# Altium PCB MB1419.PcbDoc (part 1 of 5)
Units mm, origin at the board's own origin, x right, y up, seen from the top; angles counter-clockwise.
Board outline 31 x 41 mm, 8 copper layers (Top Layer, Signal Layer 1, Signal Layer 2, Signal Layer 3, Signal Layer 4, Signal Layer 5, Signal Layer 6, Bottom Layer), stack 1.536 mm thick; 212 components, 125 nets, 637 pads, 2405 vias.
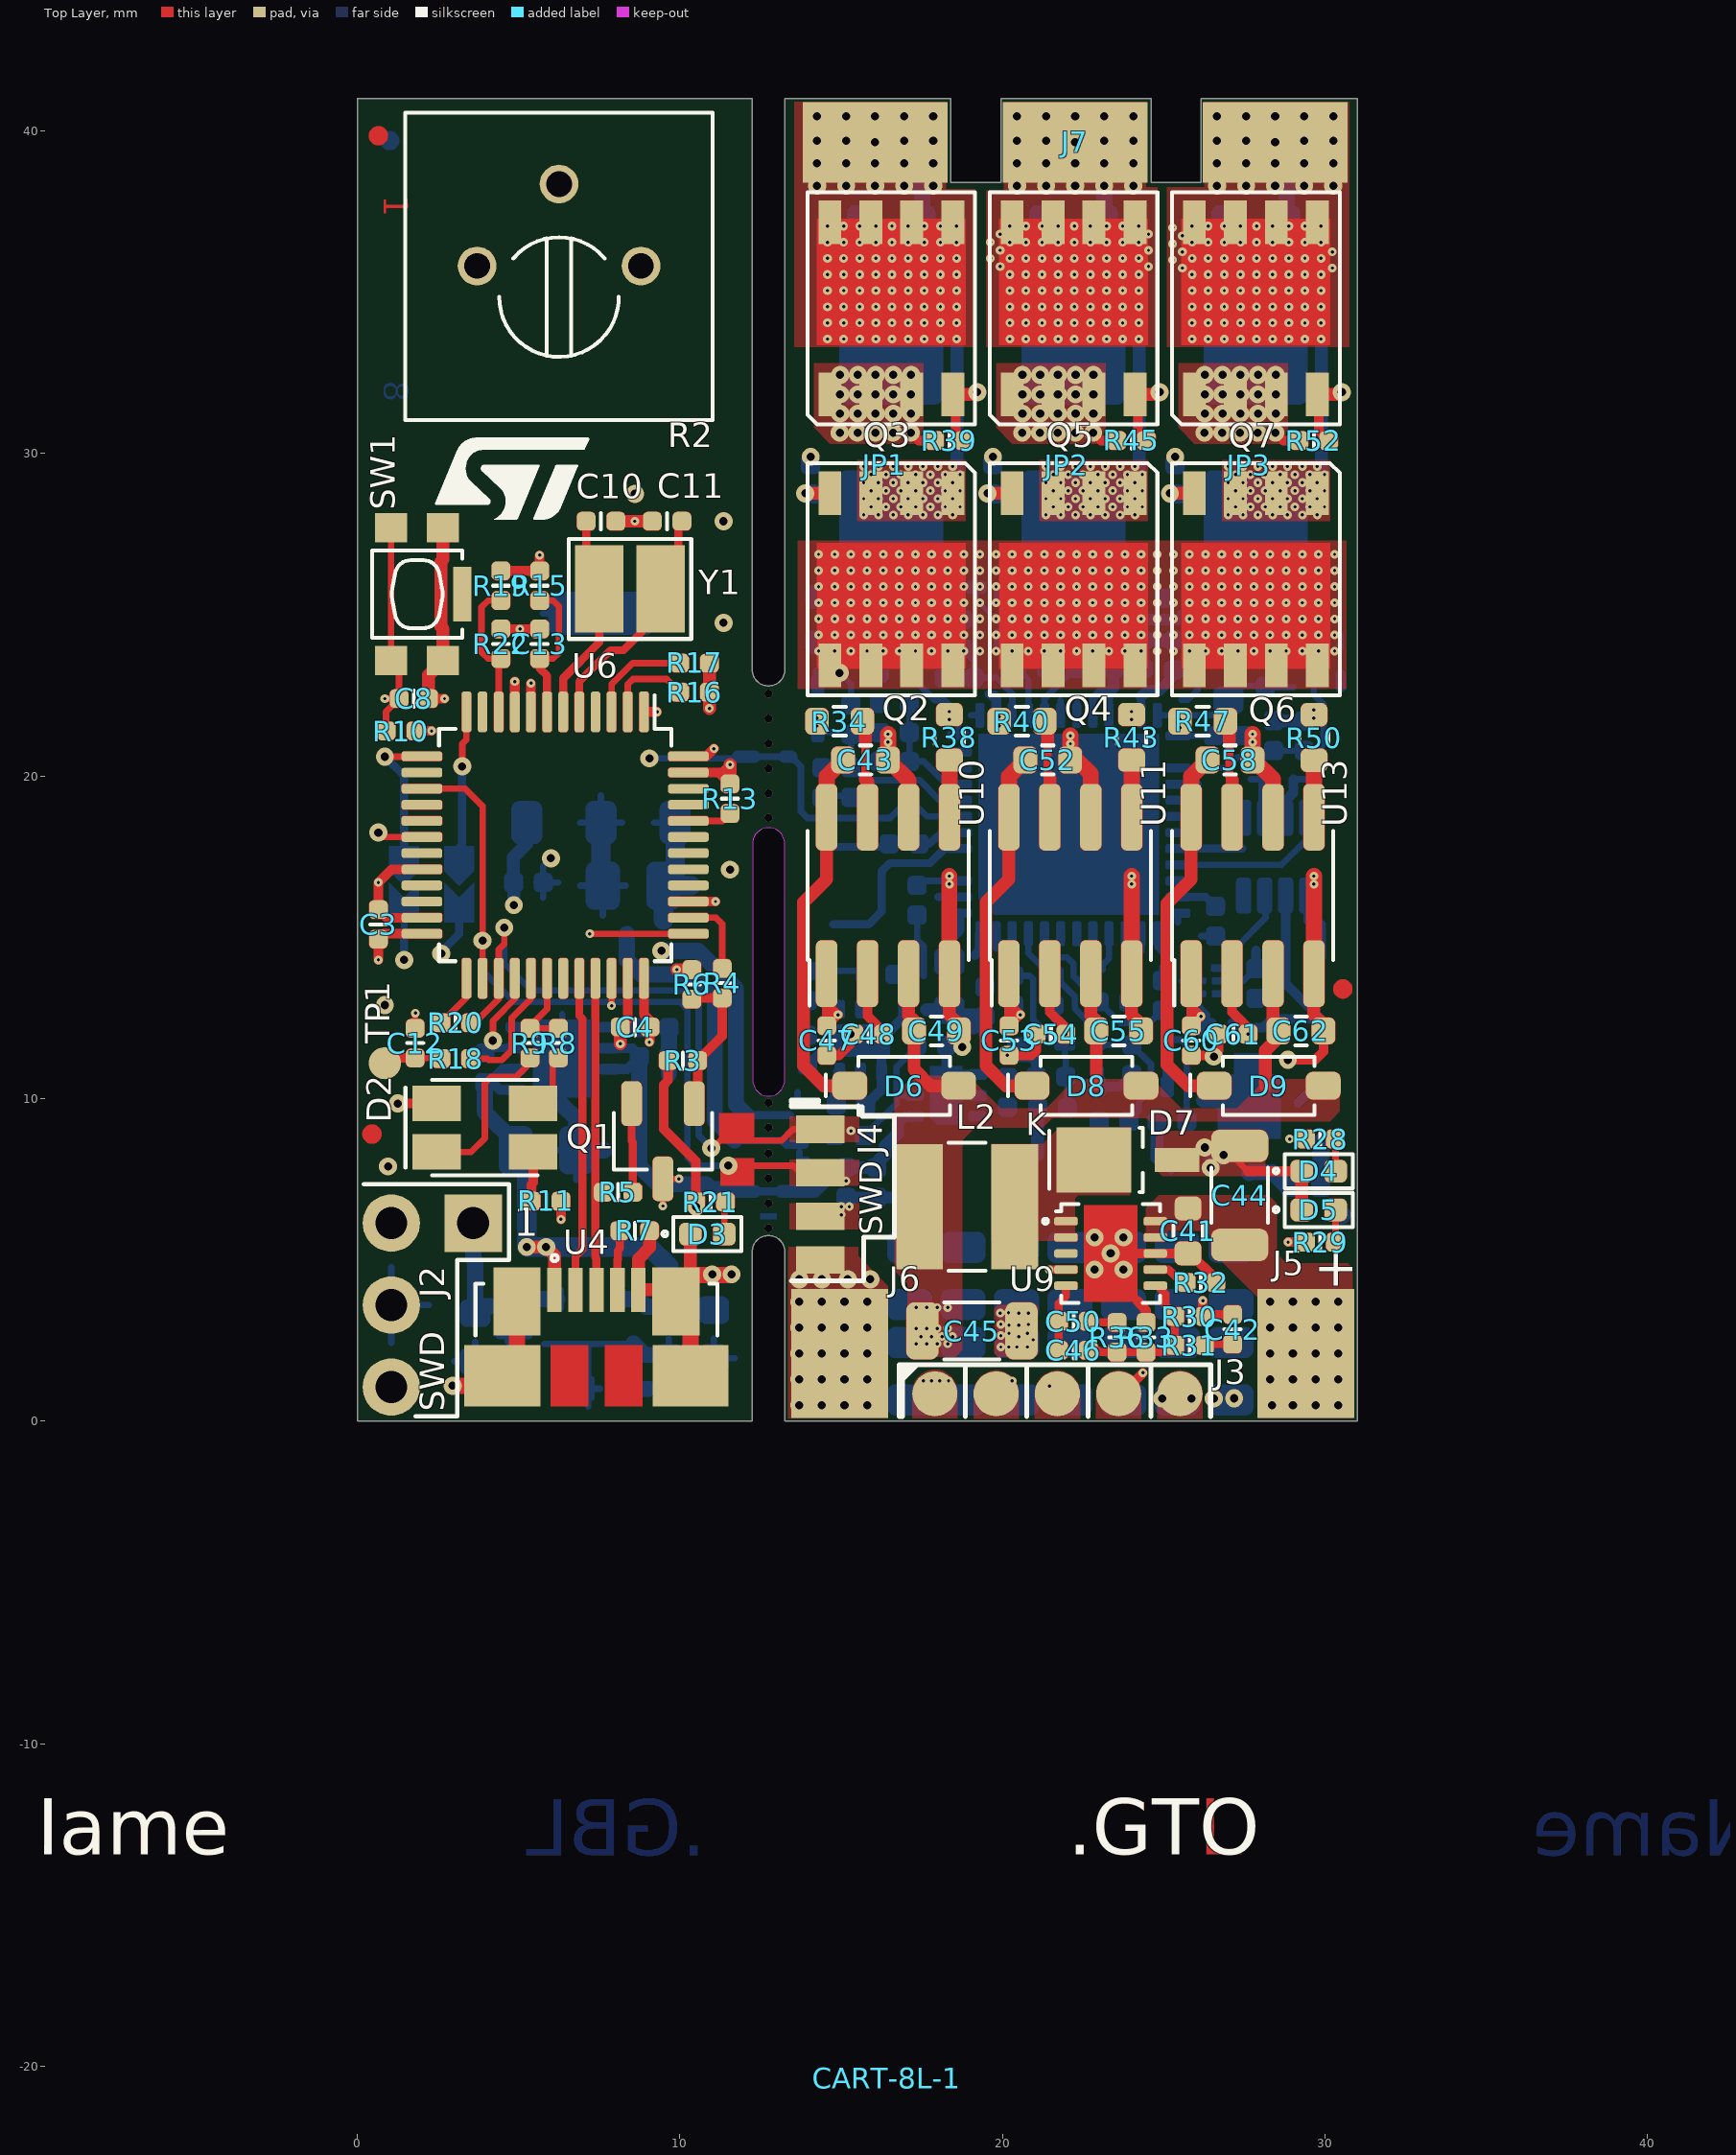
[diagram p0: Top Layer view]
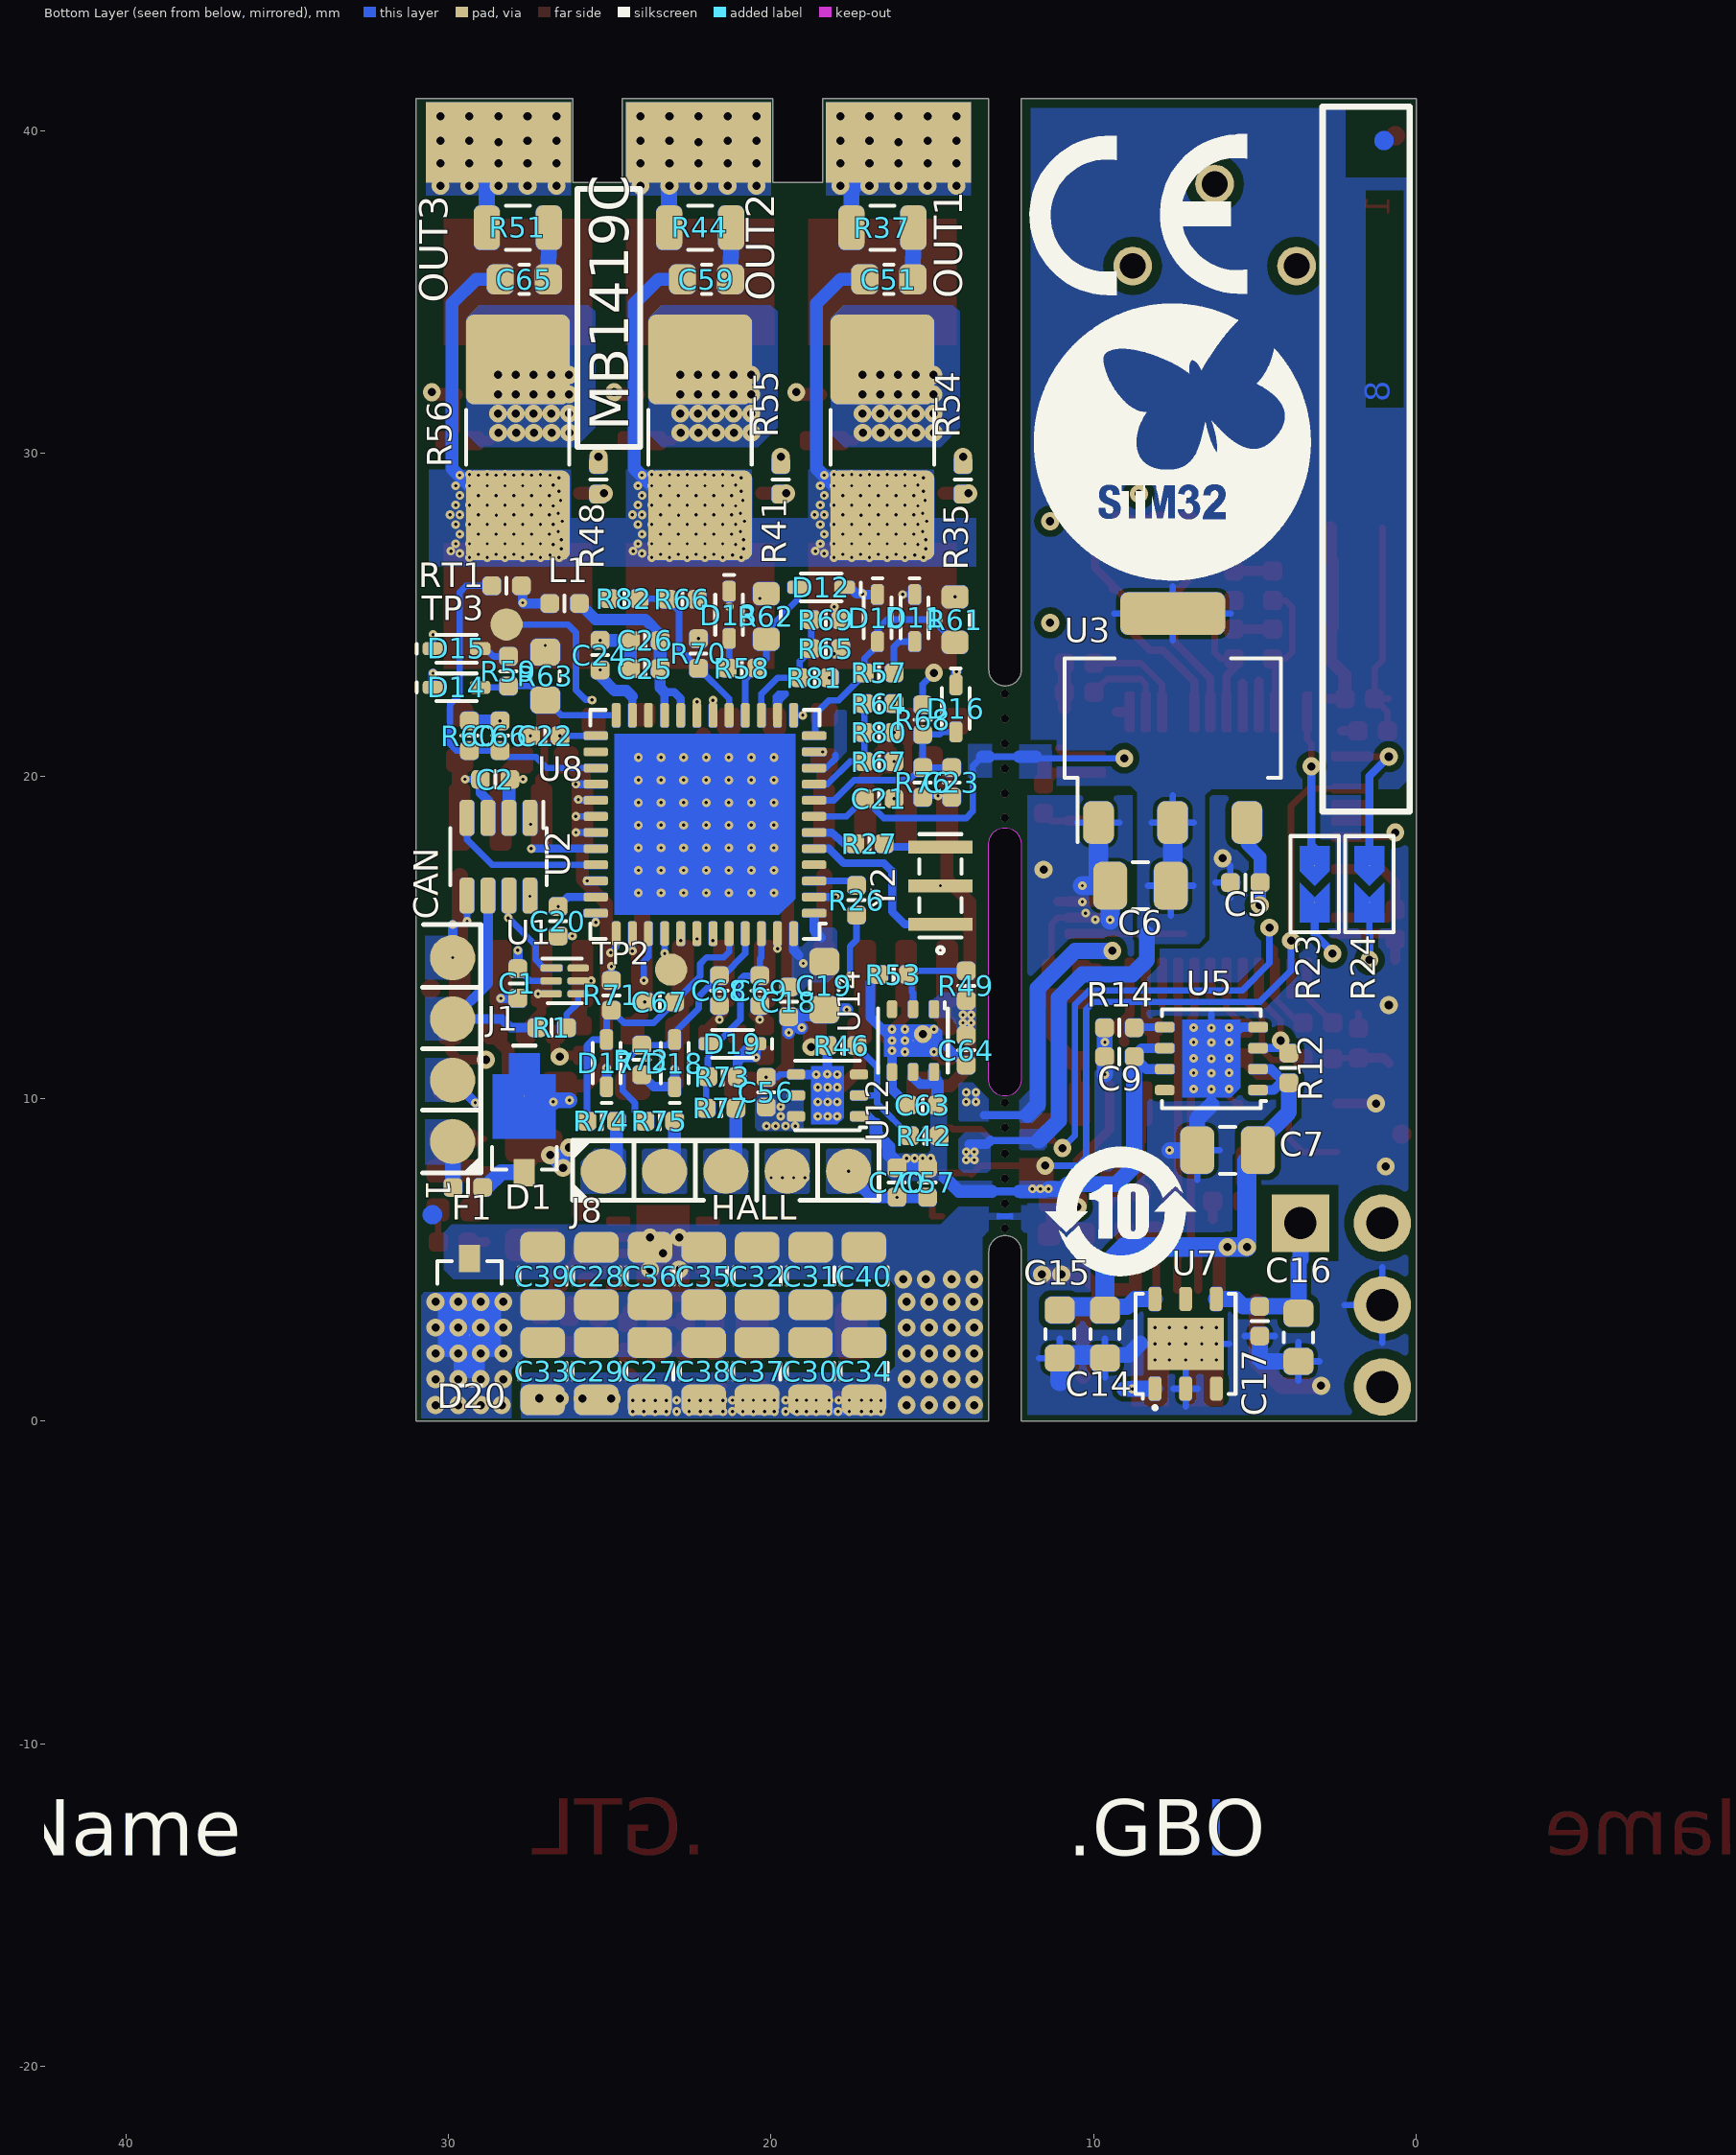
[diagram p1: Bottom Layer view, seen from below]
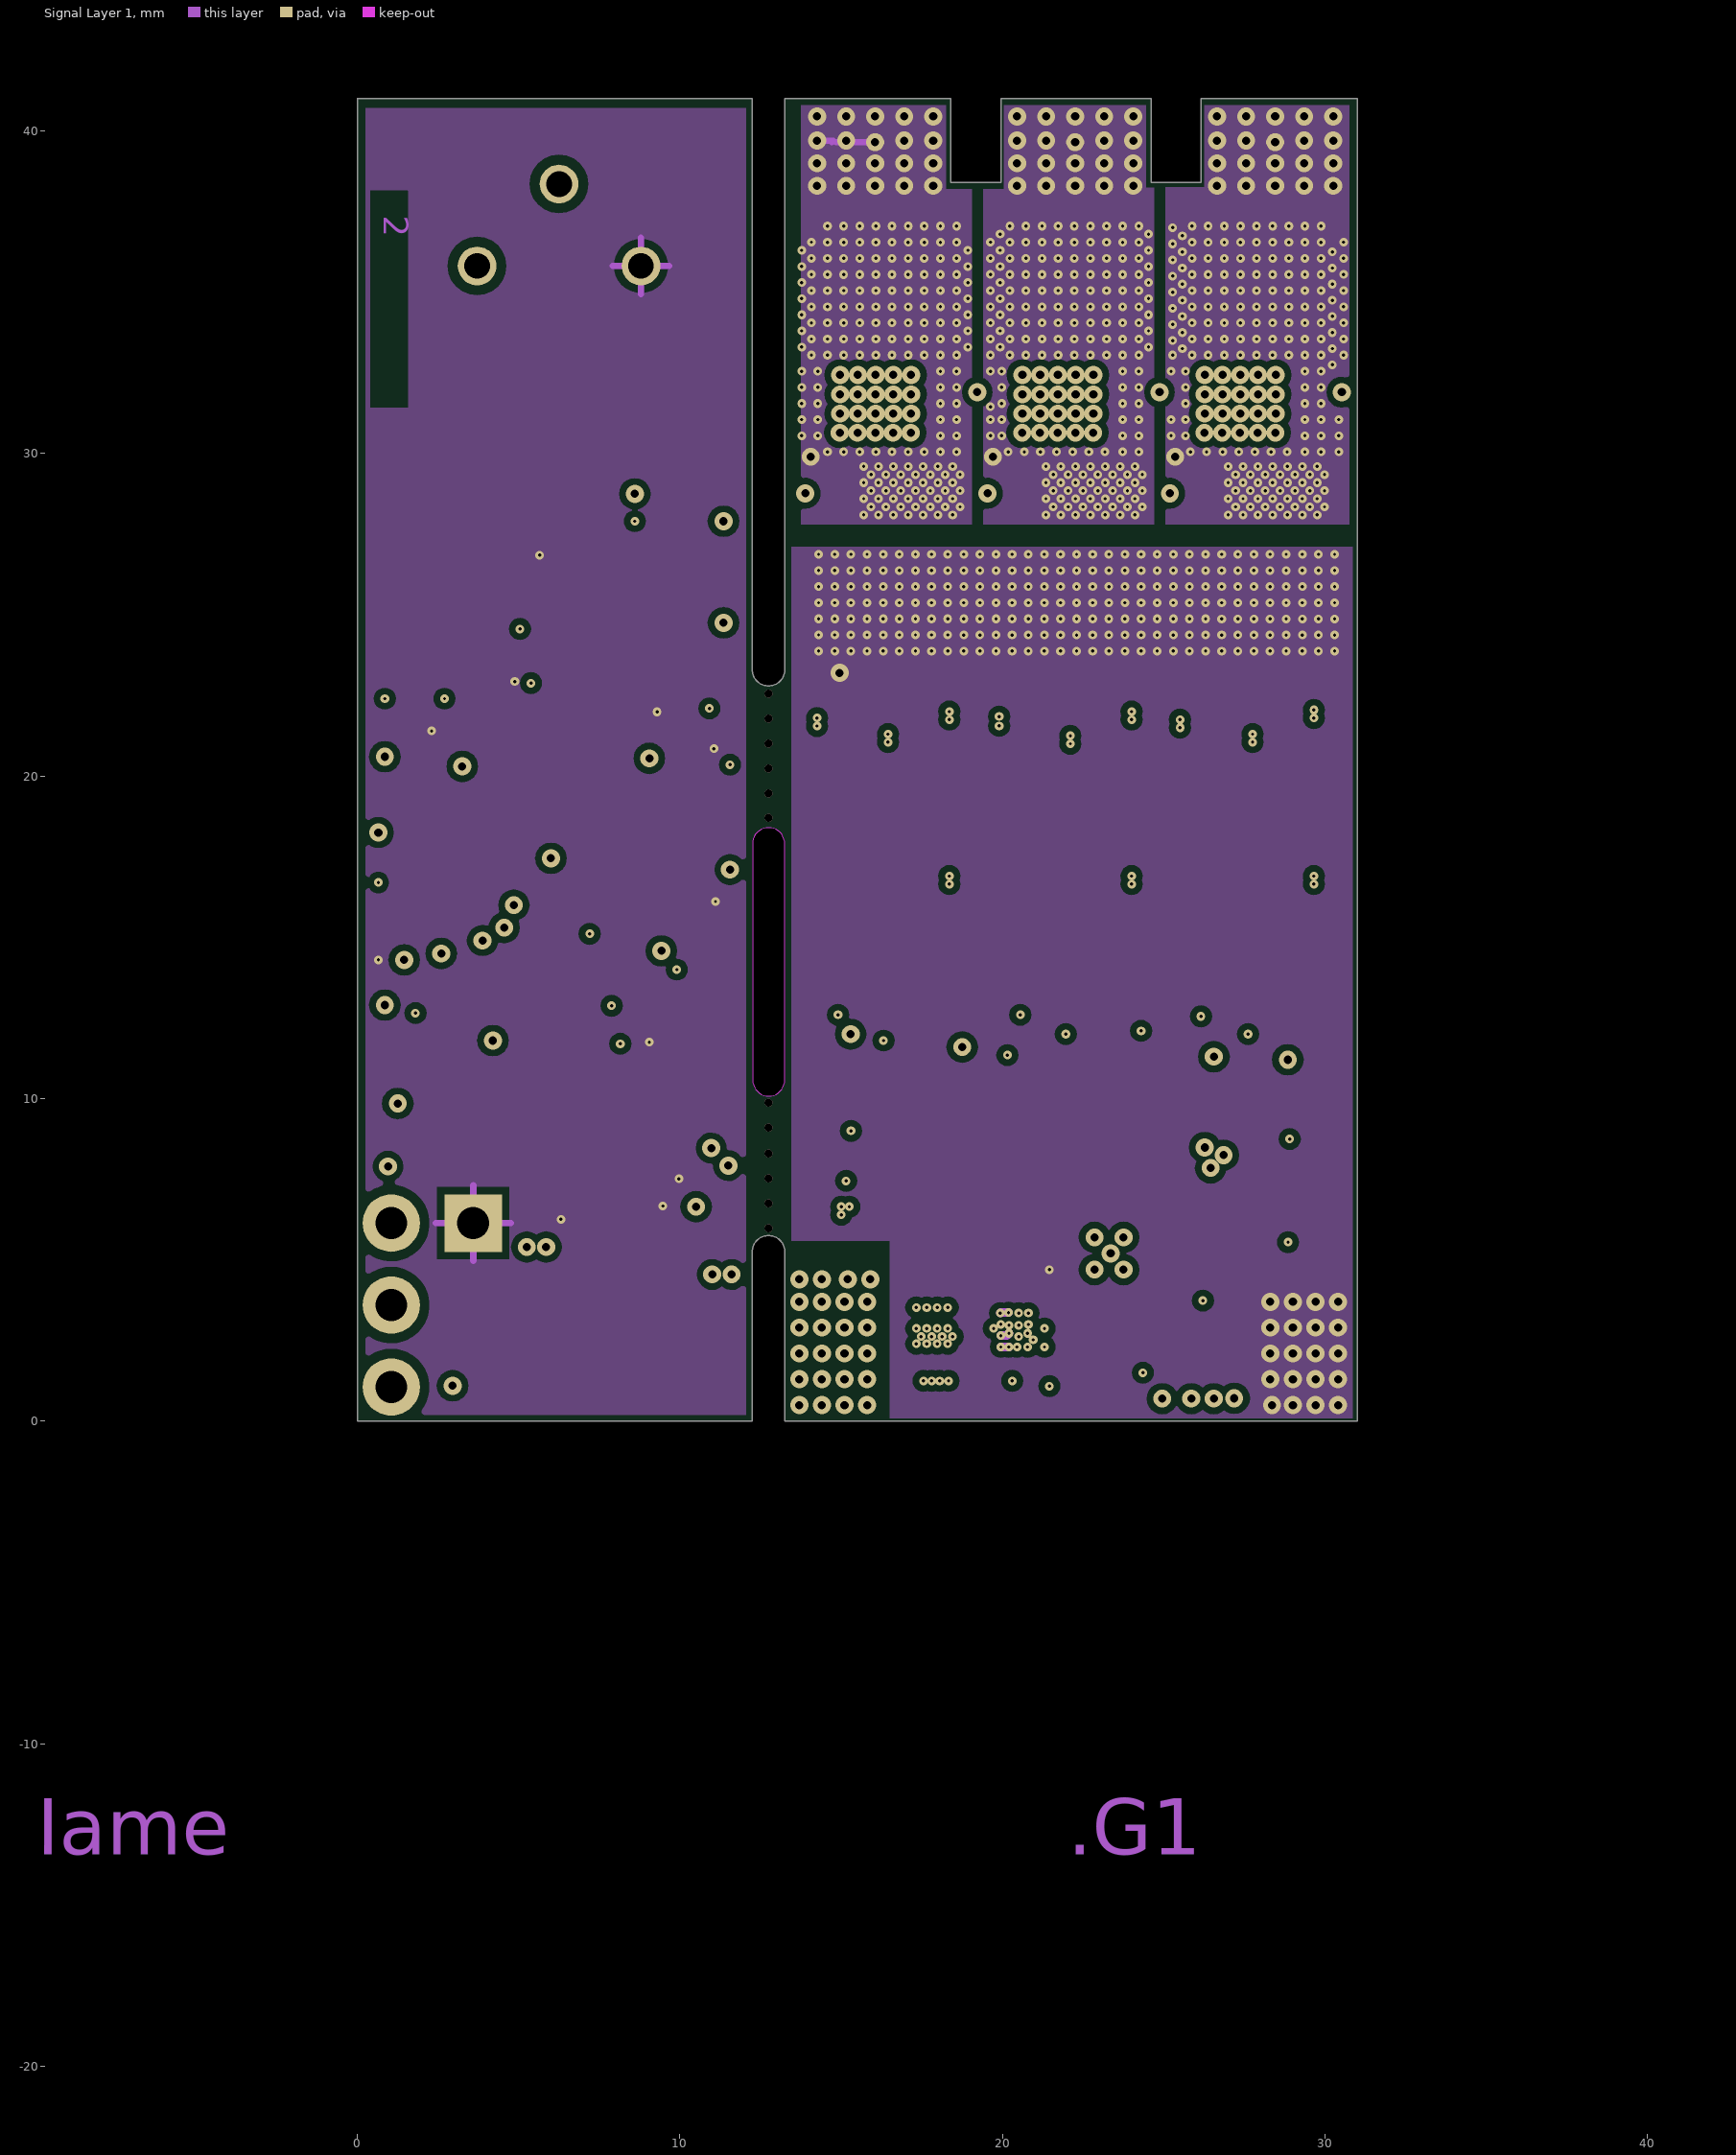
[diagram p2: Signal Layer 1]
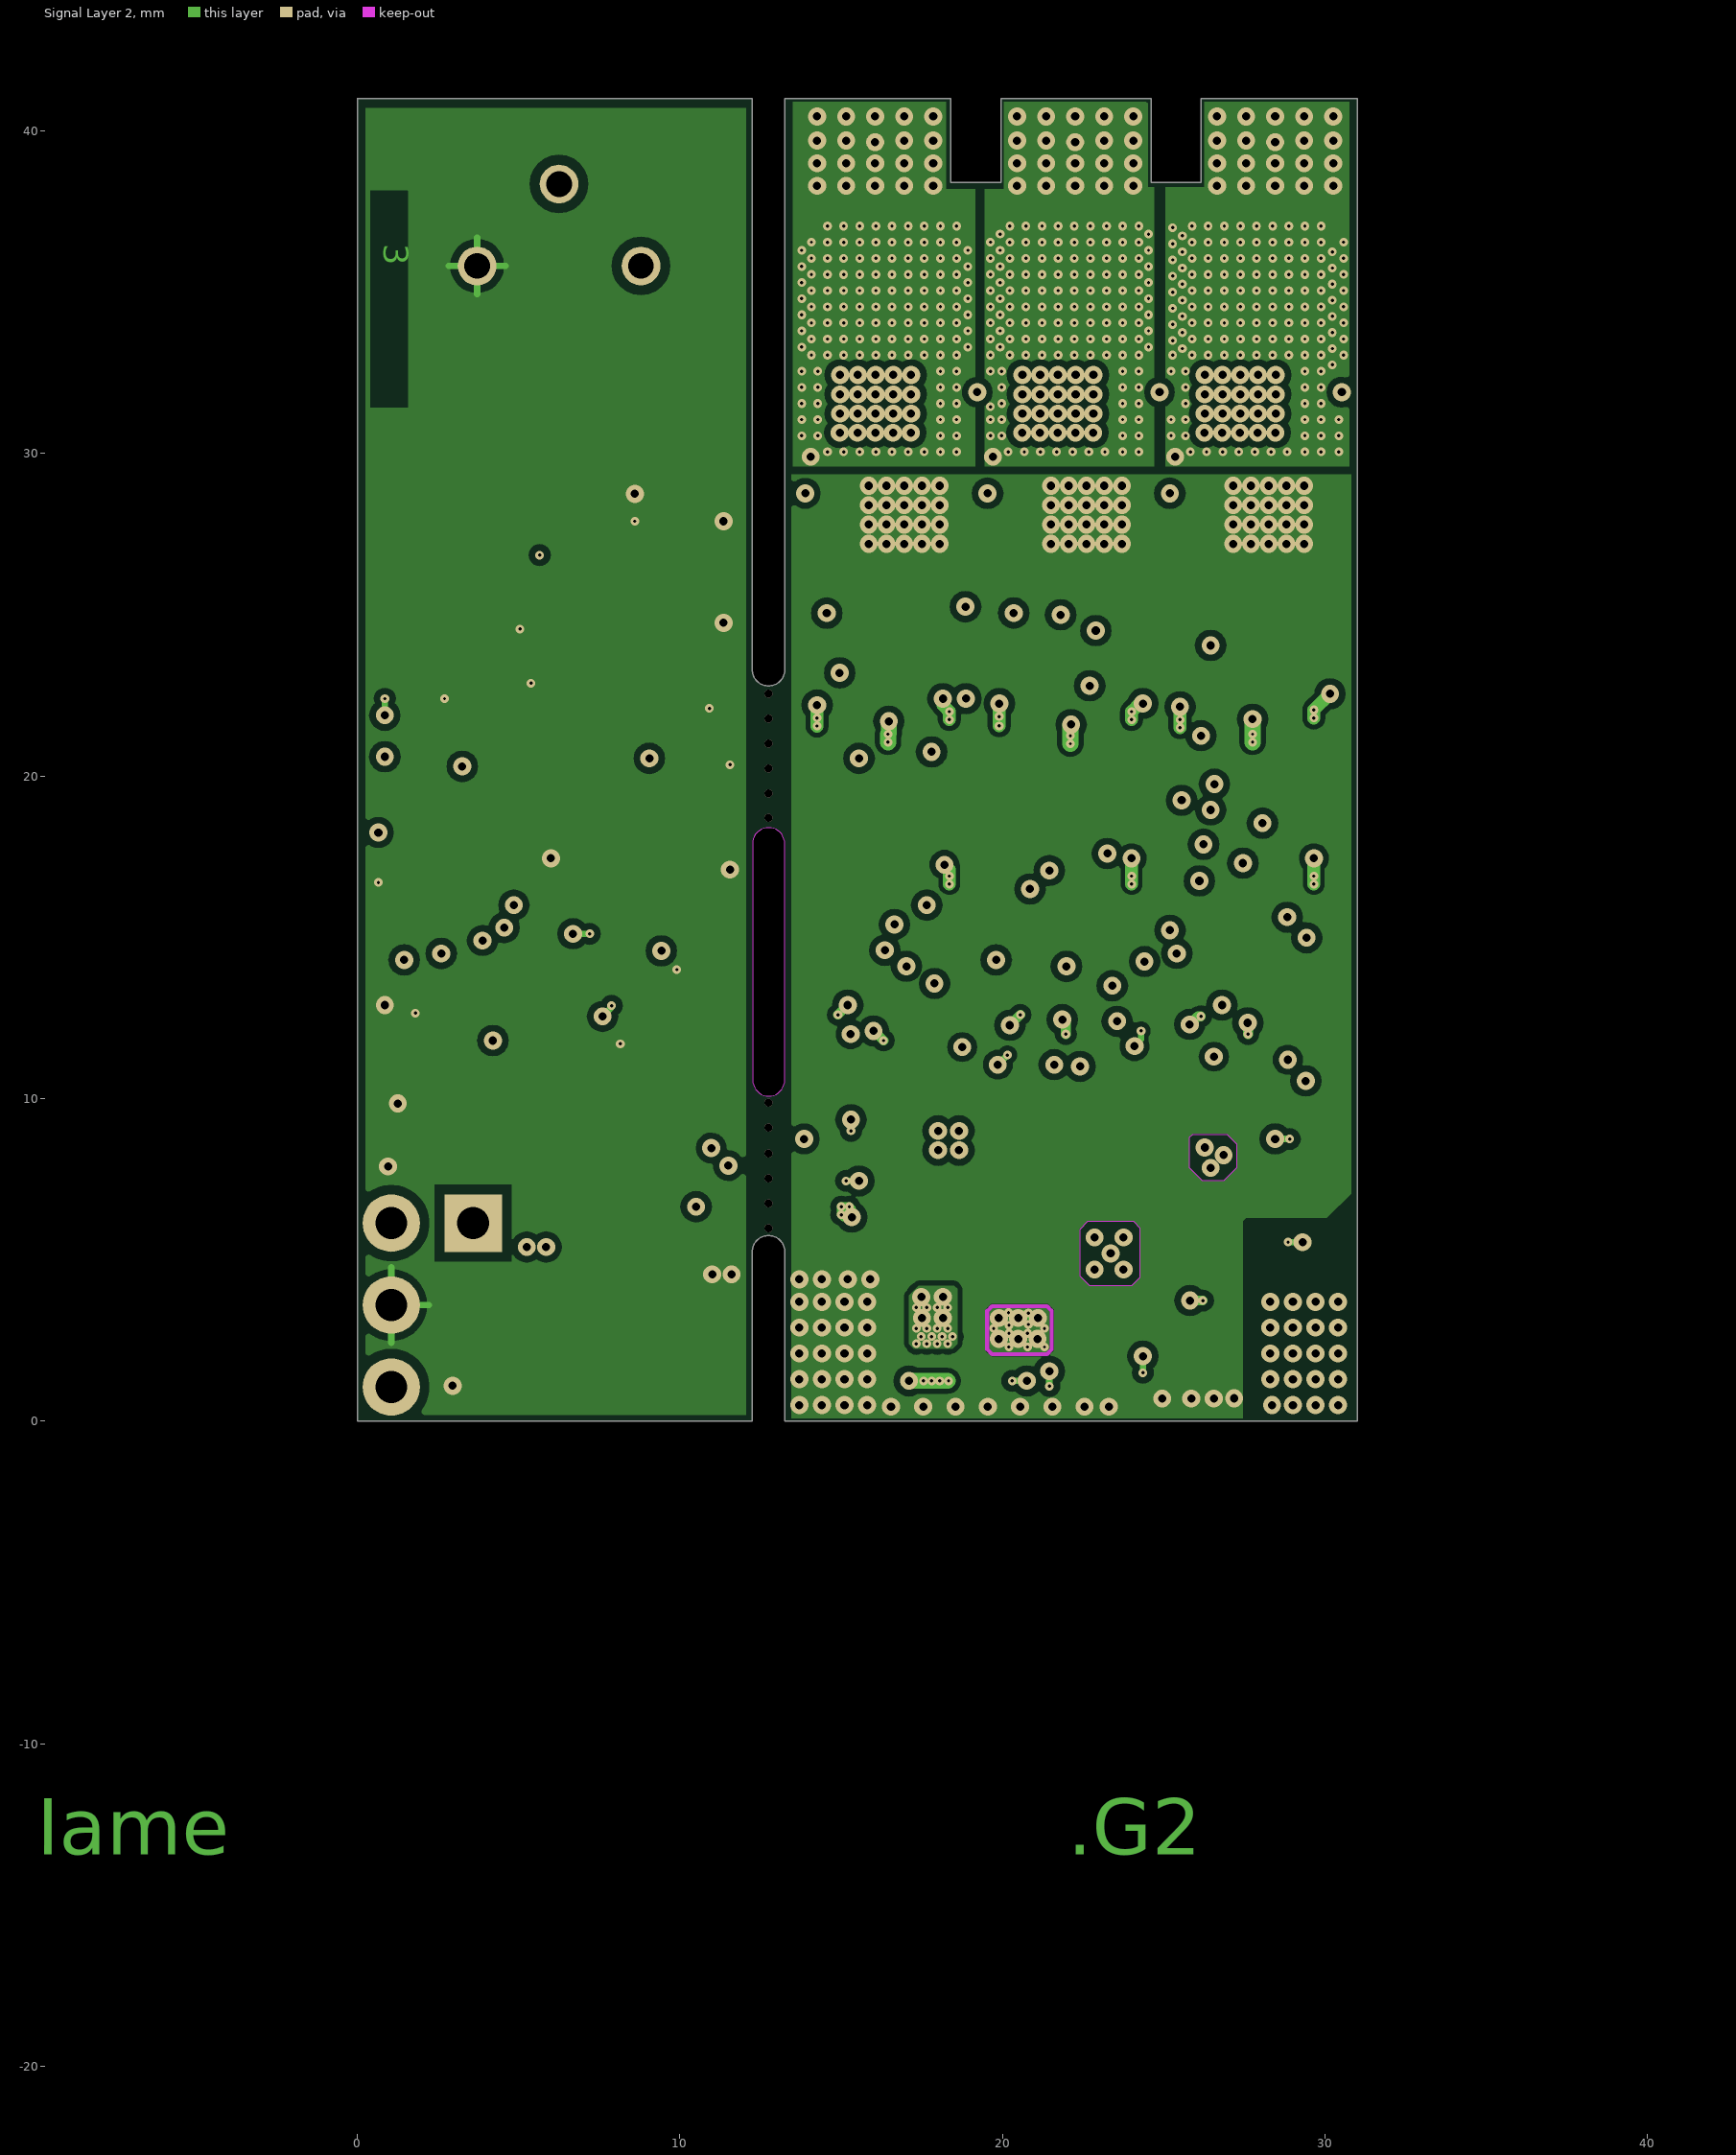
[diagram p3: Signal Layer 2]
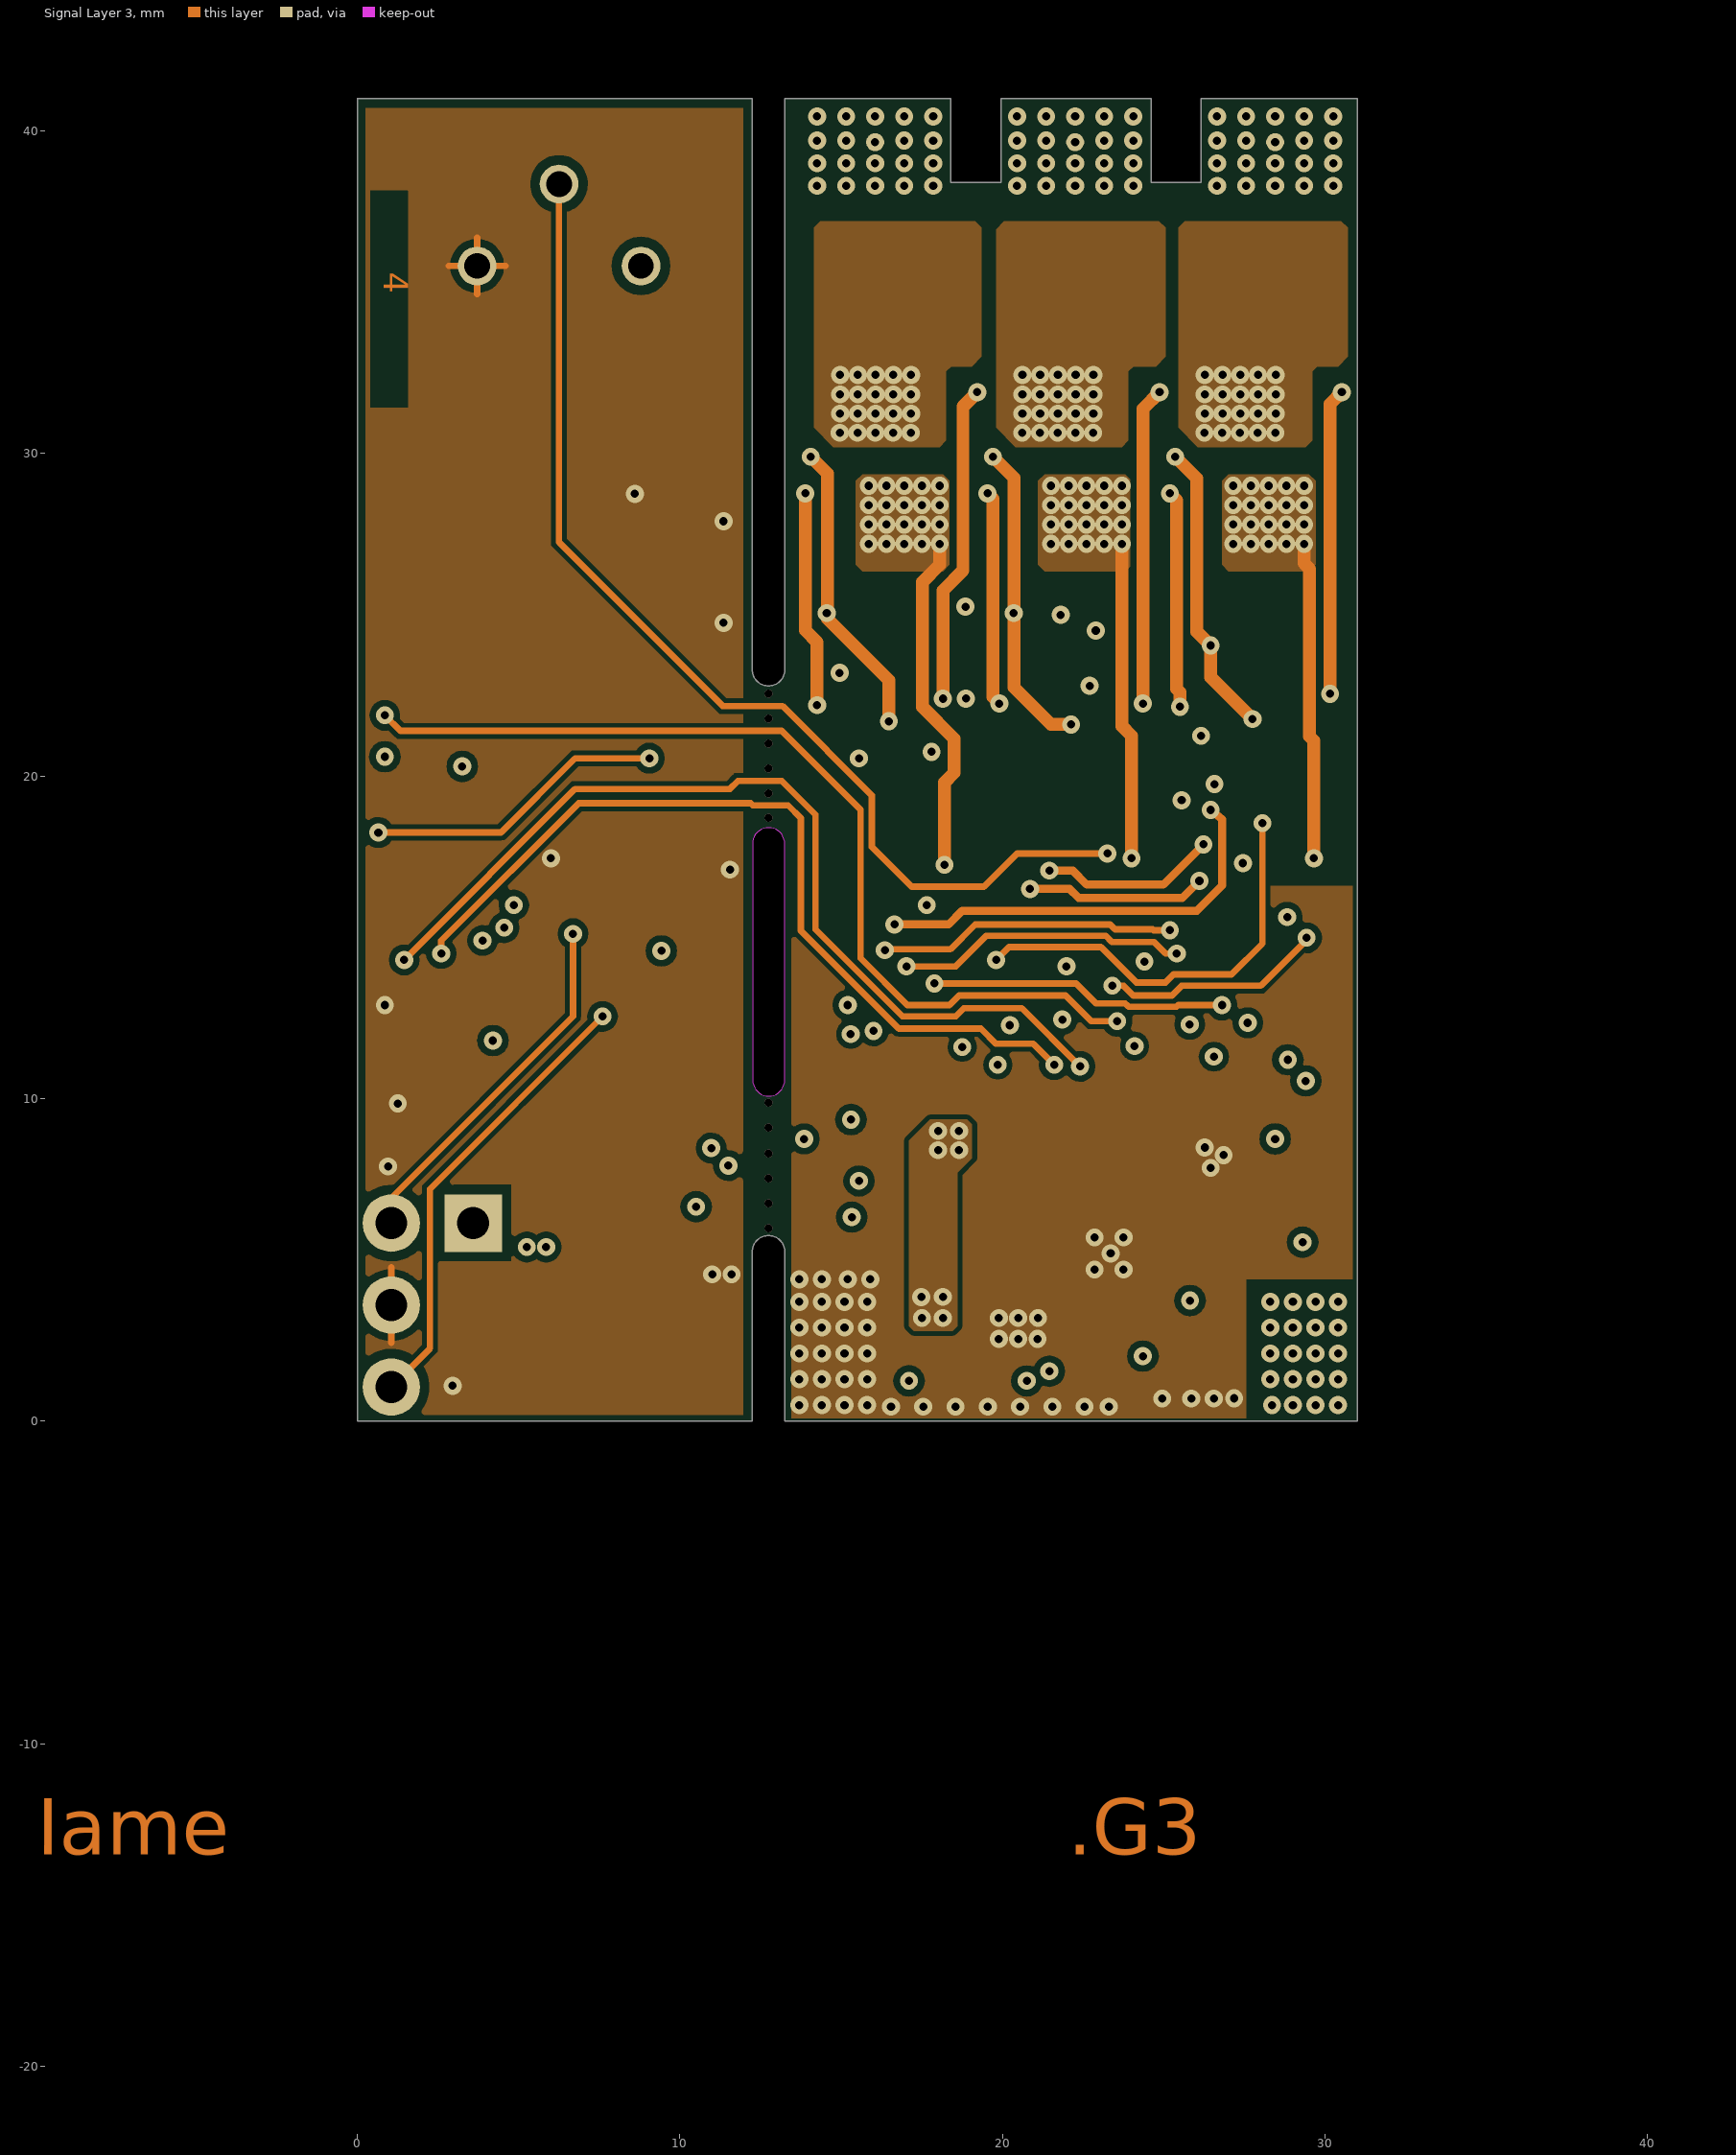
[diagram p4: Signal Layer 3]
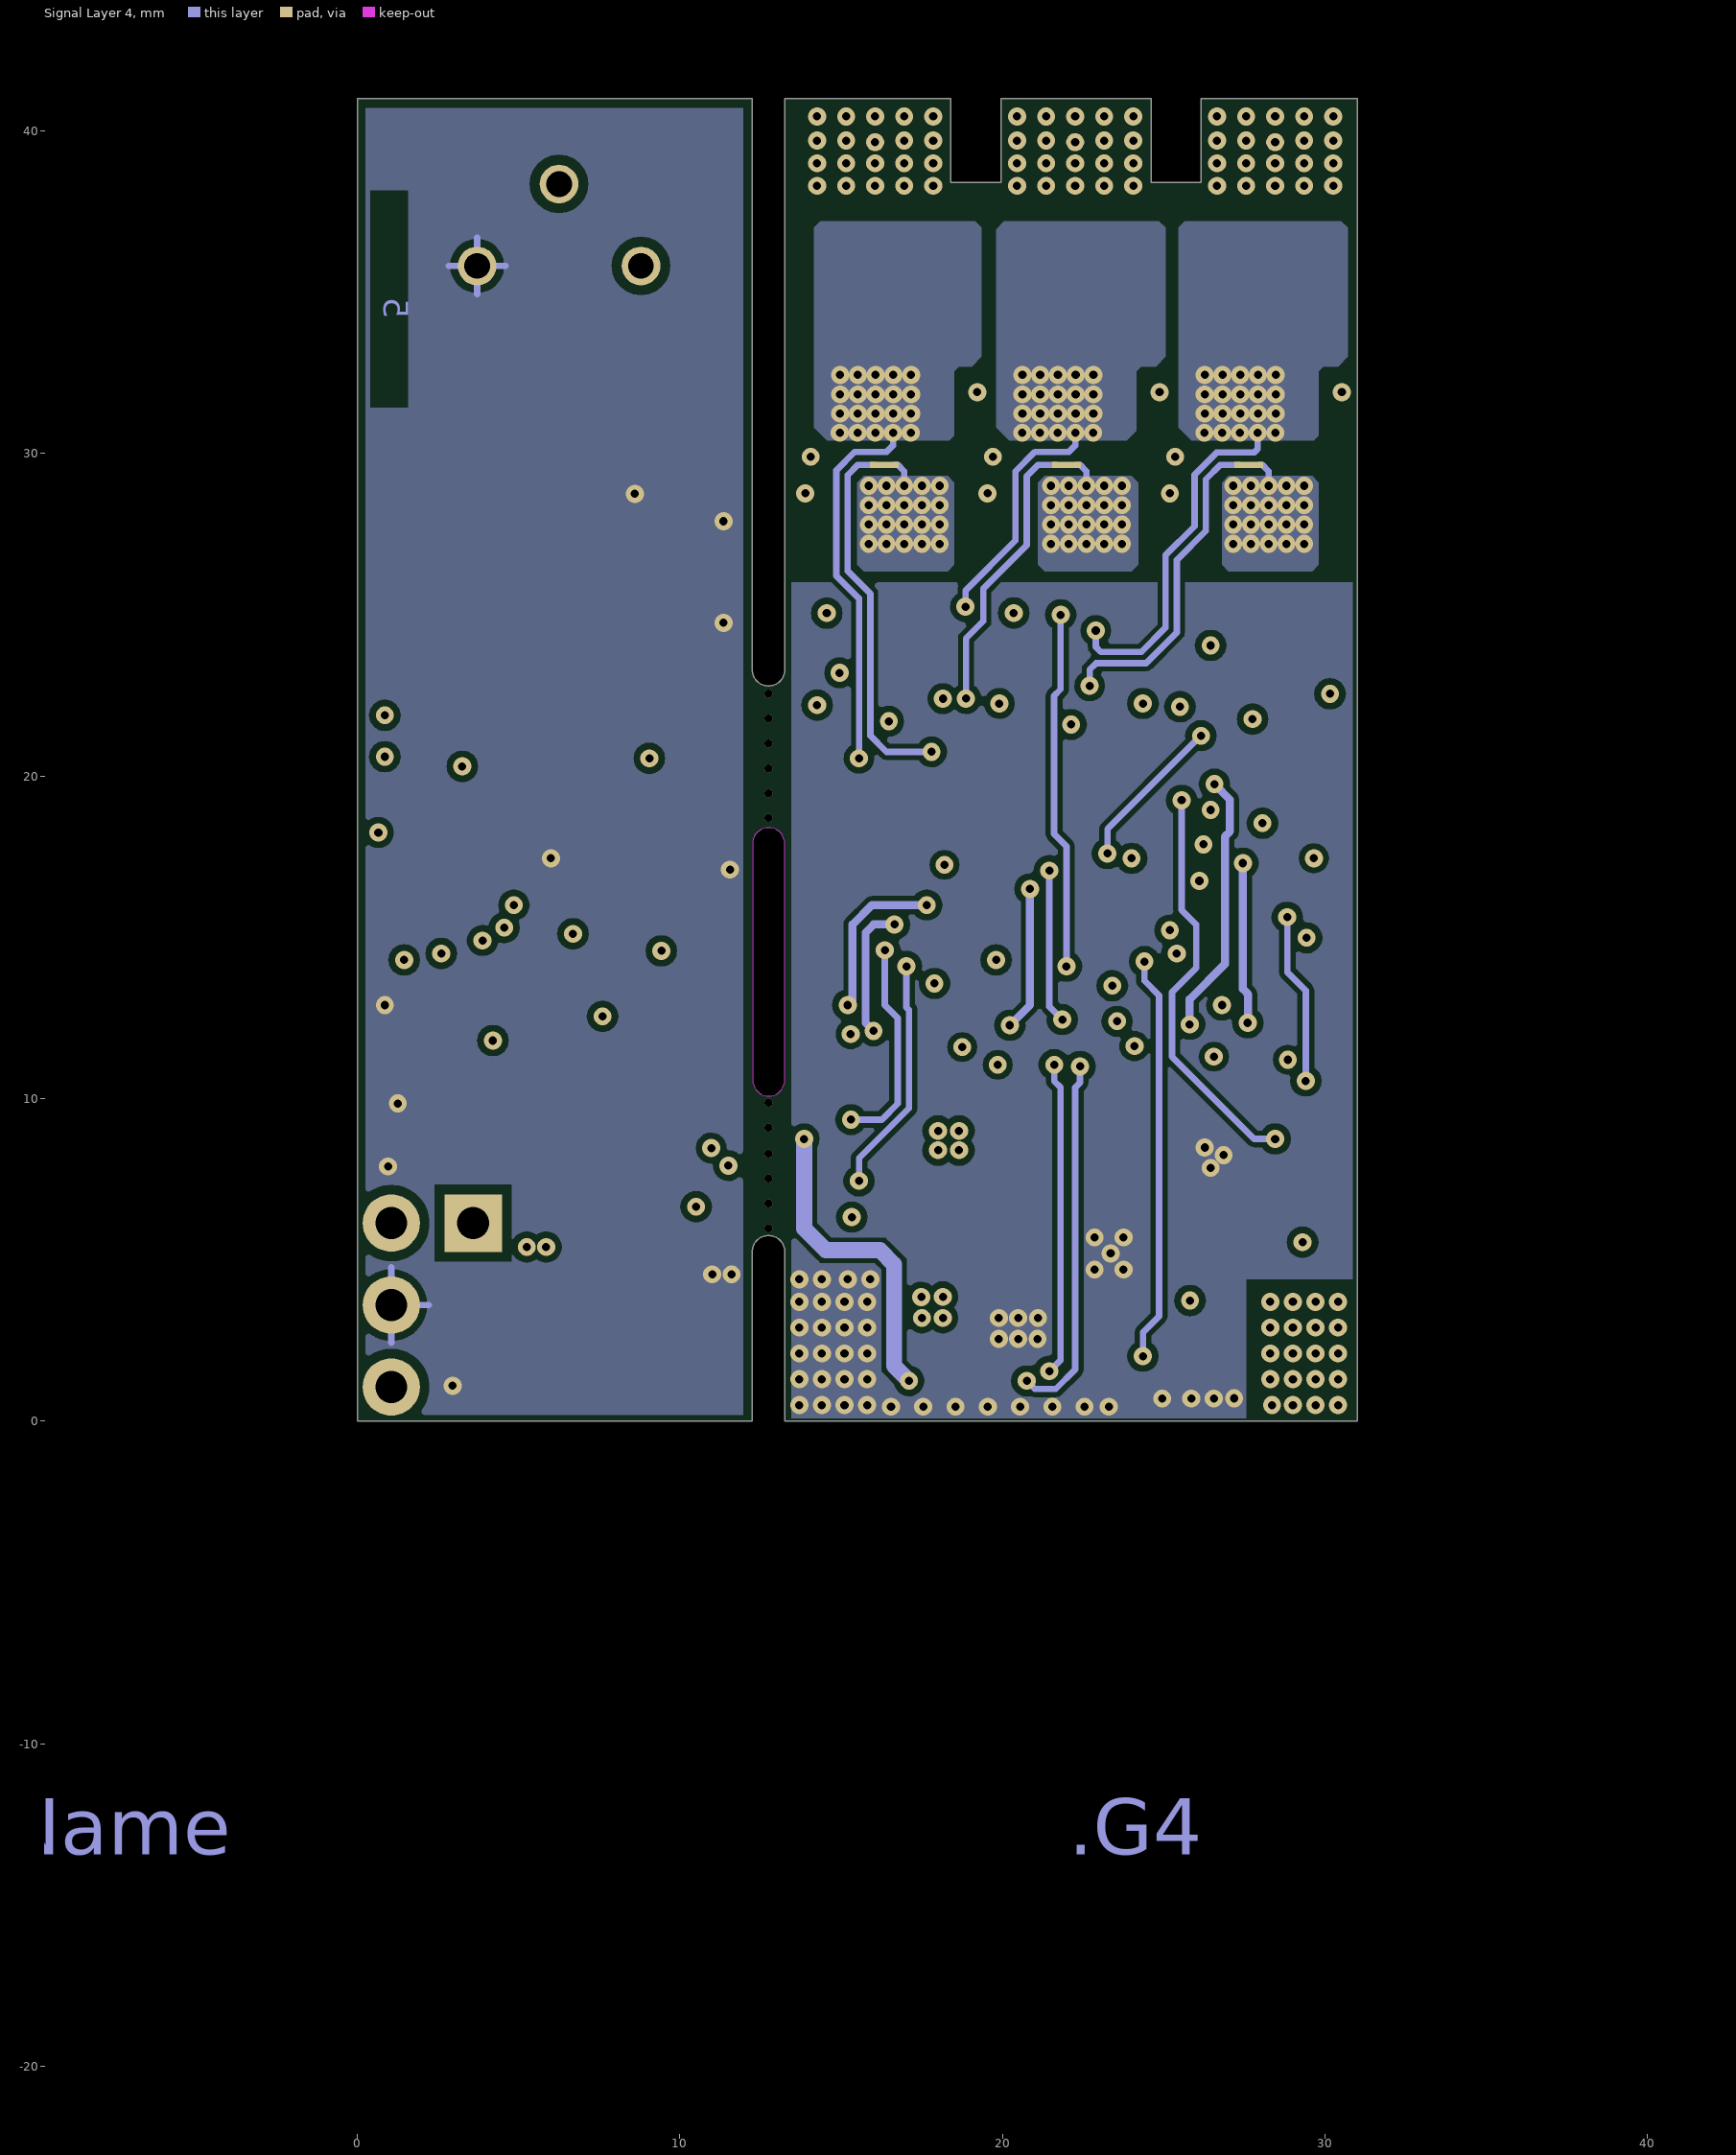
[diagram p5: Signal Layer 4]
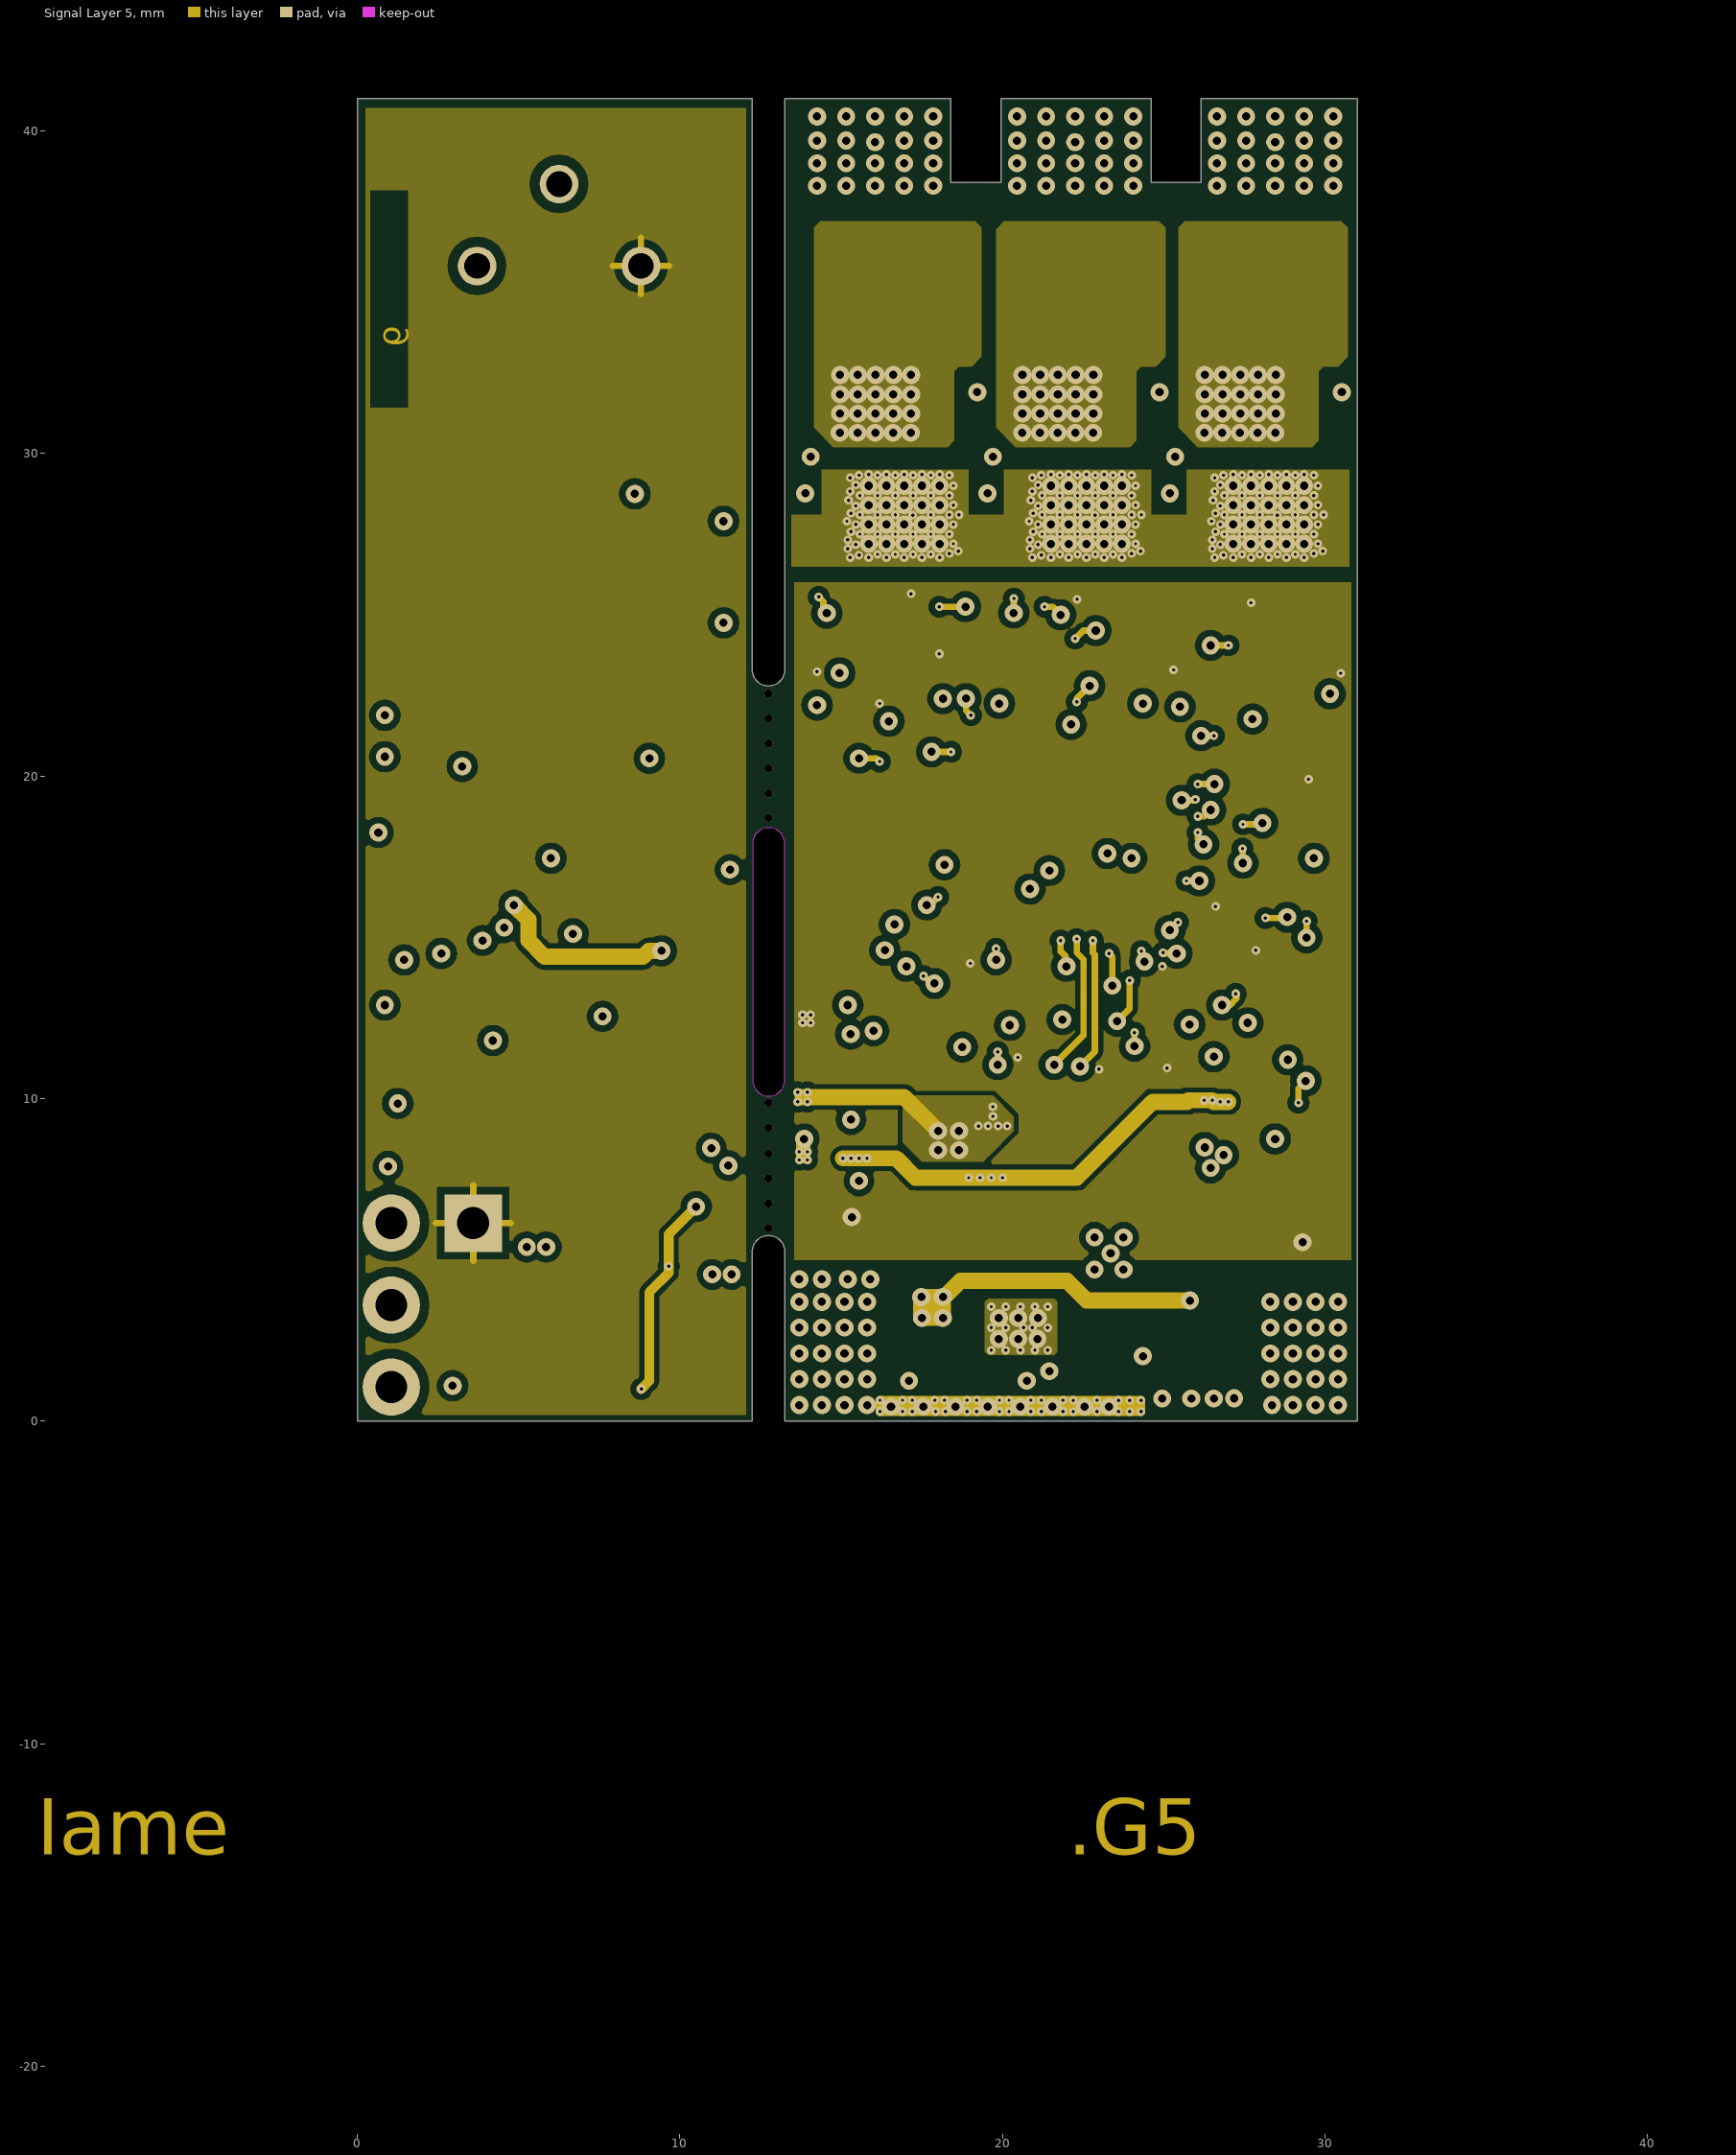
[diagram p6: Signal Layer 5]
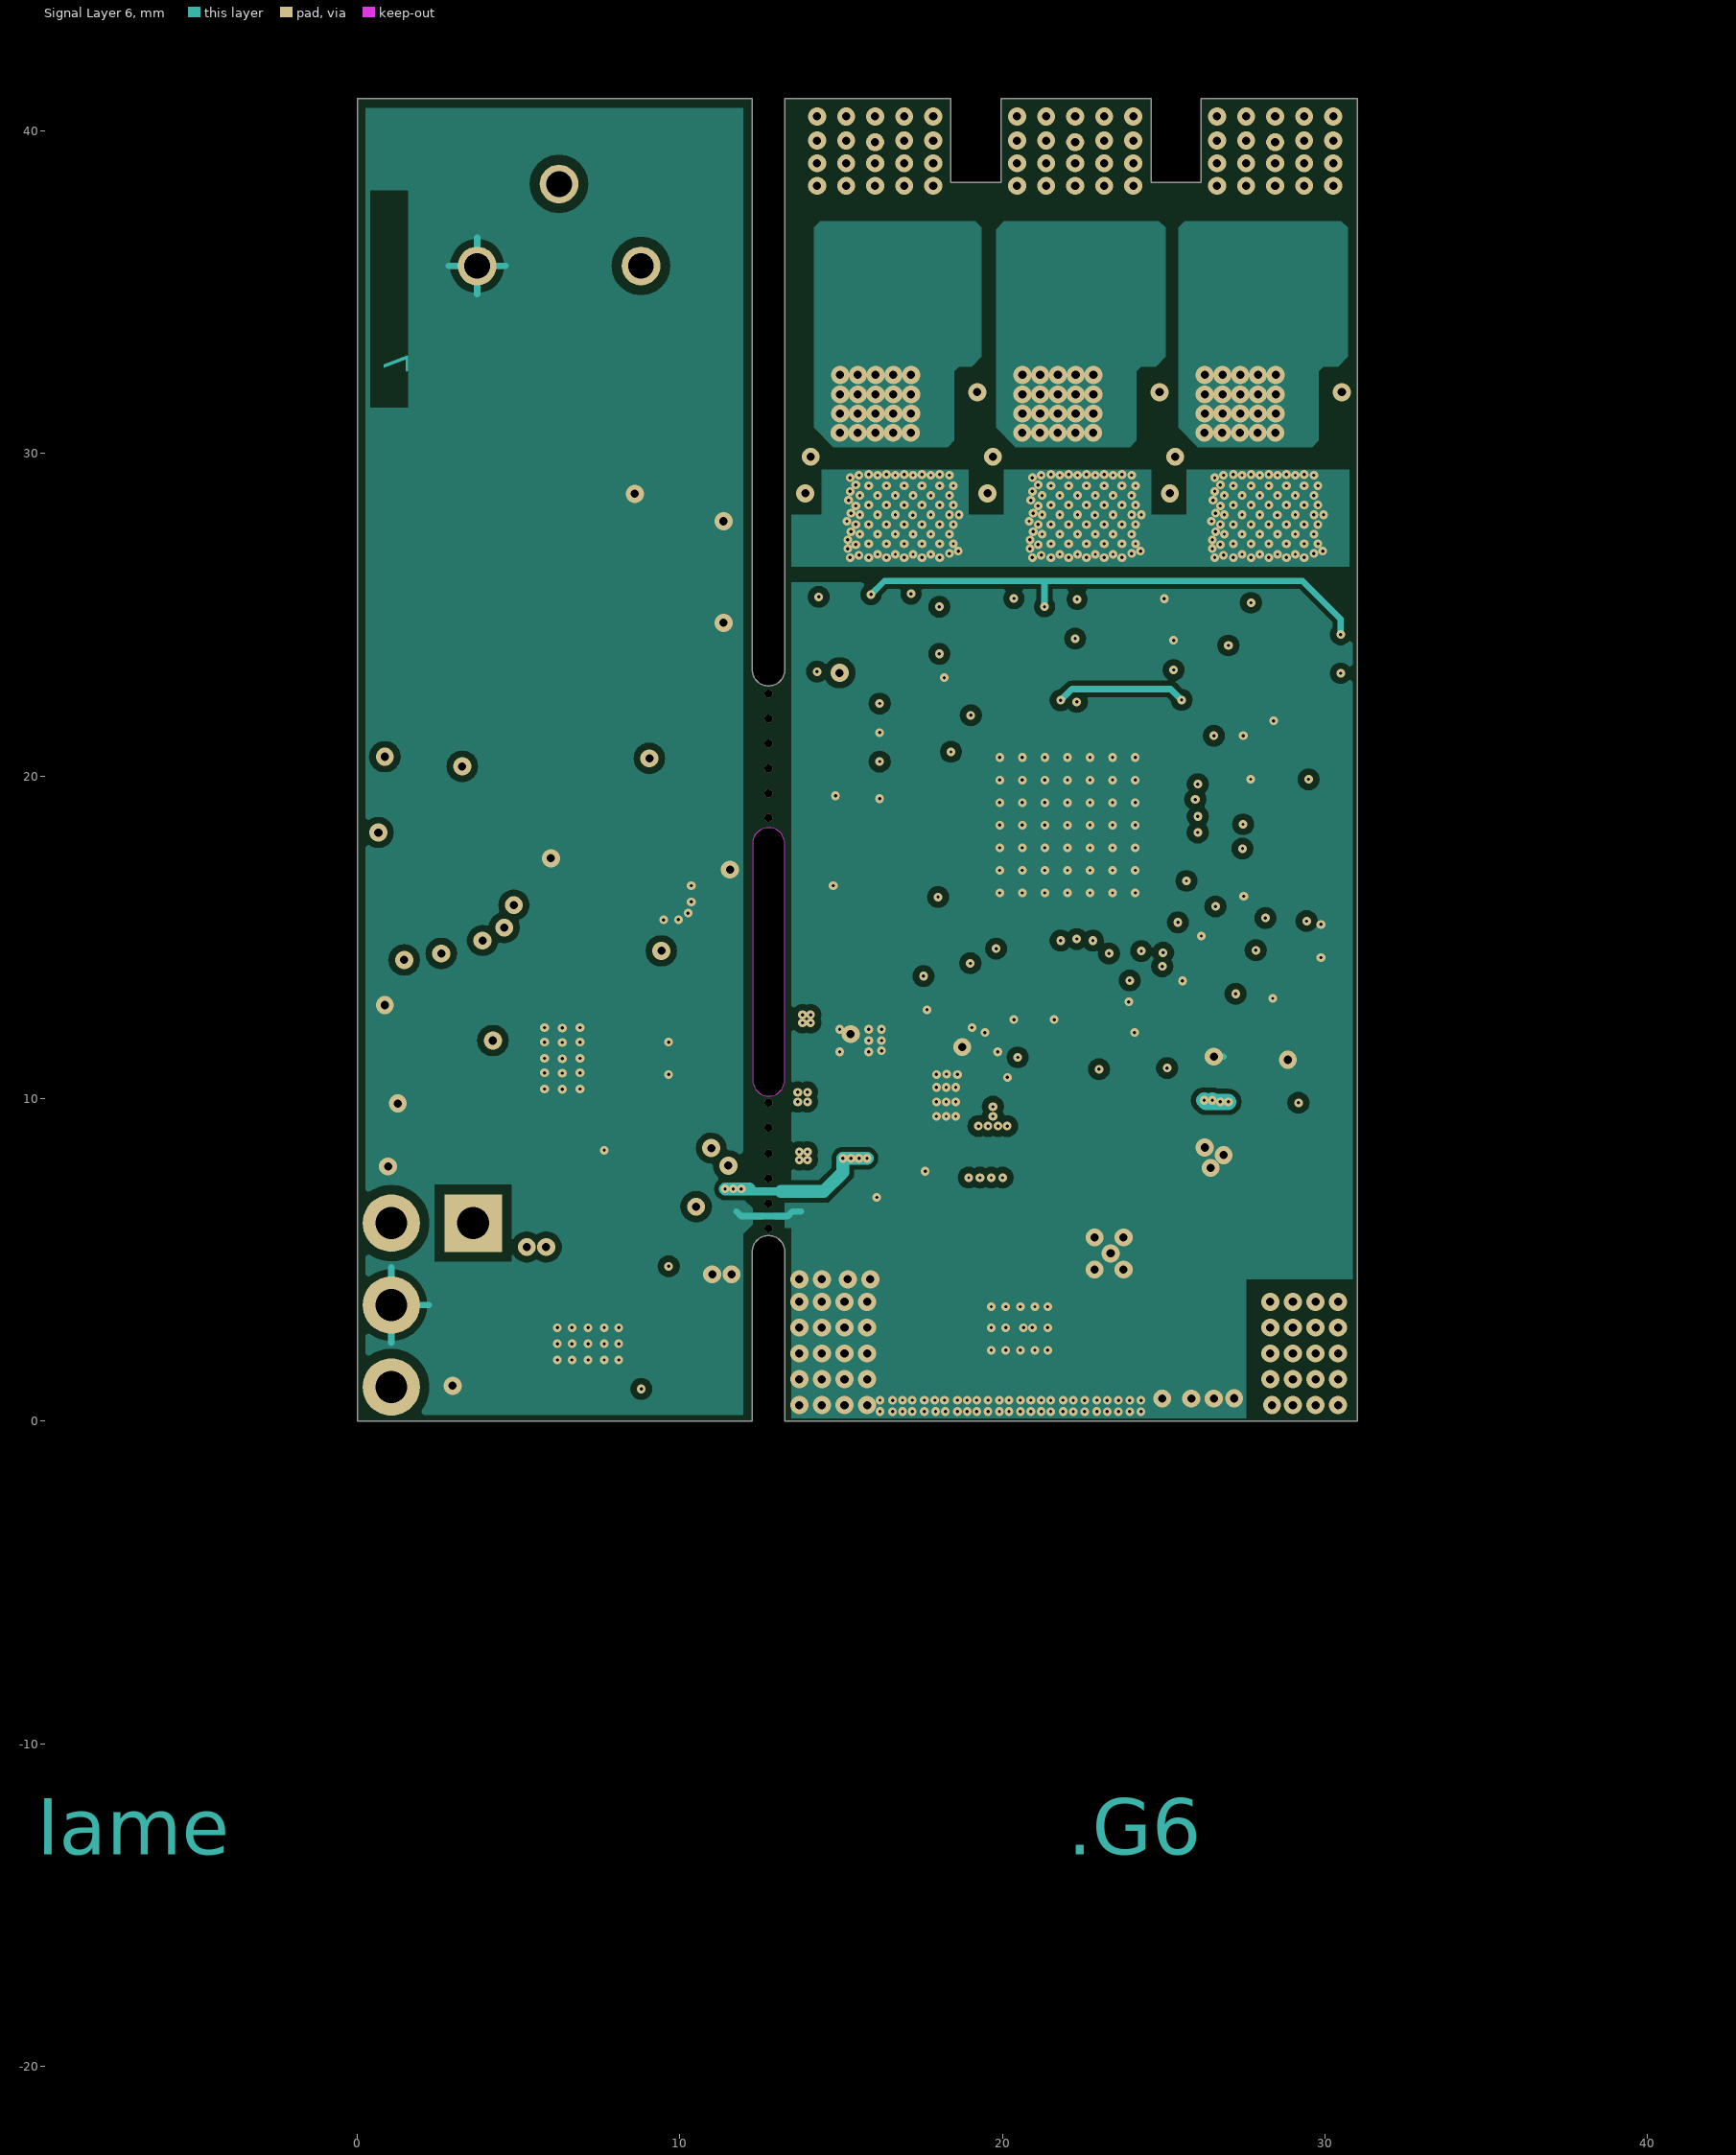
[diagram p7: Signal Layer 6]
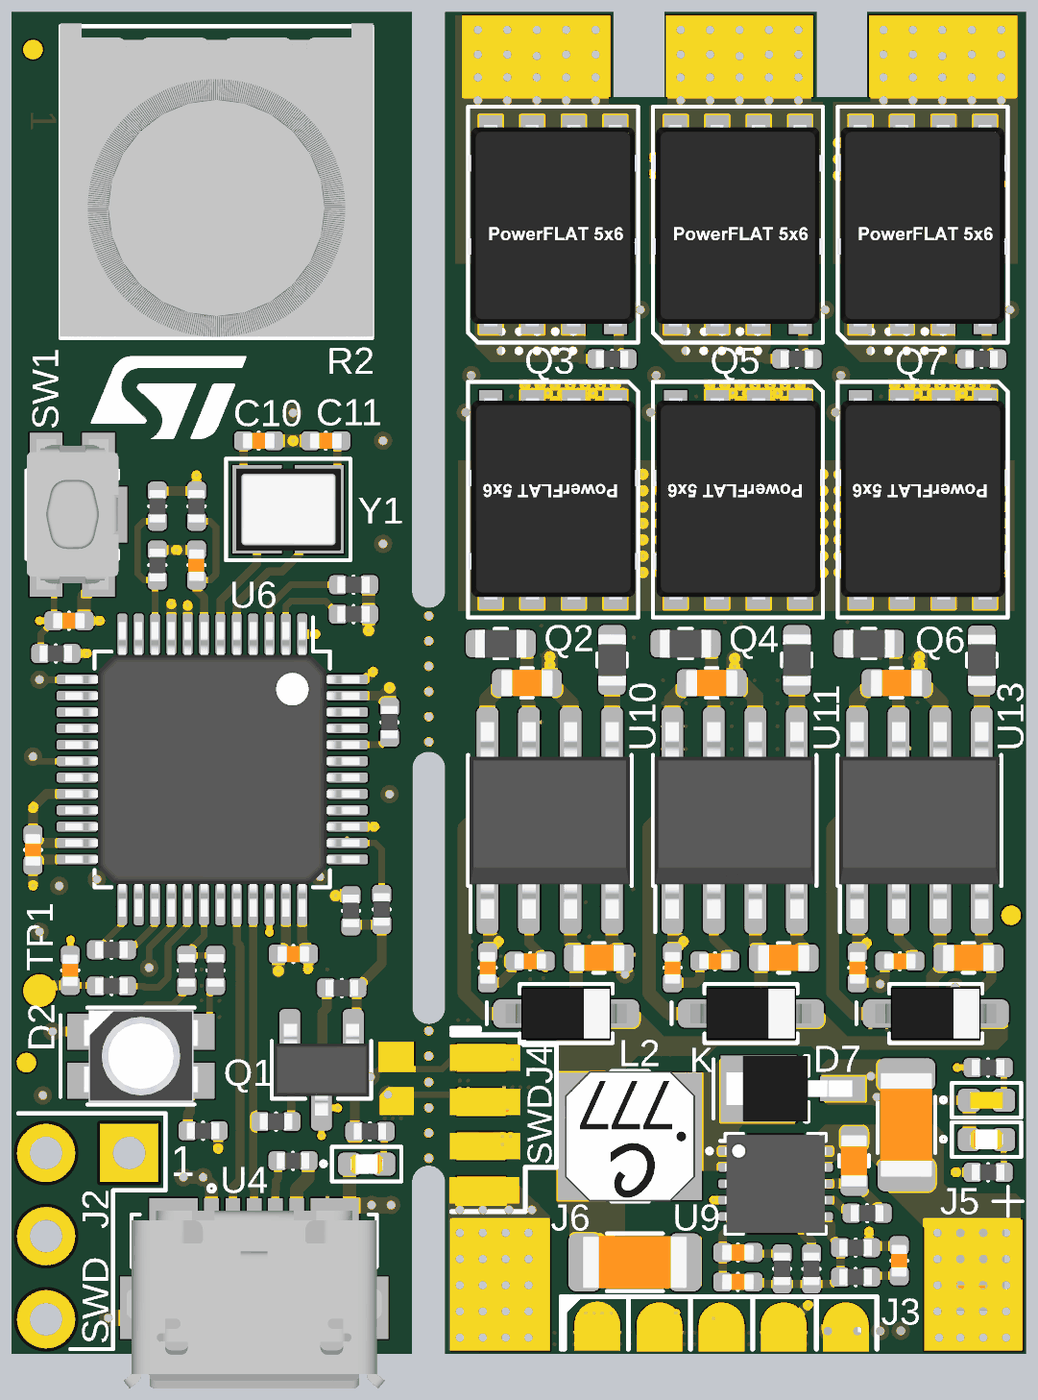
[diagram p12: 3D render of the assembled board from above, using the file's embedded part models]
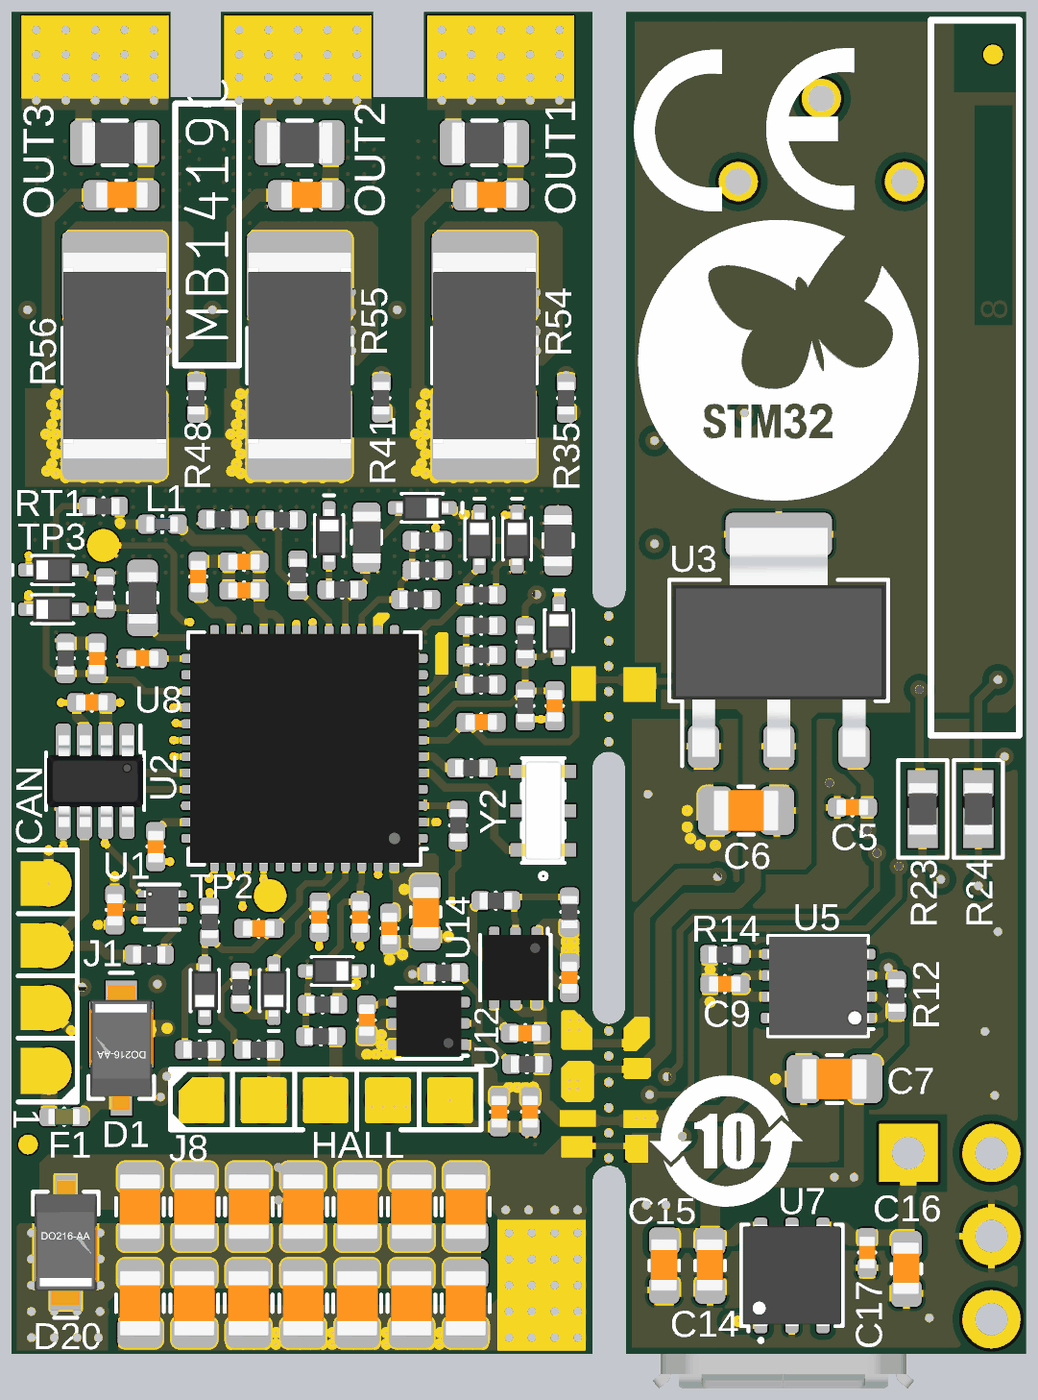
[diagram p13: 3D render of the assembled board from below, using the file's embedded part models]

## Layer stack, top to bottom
Top Solder: solder mask 0.0102, Solder Resist, Dk 3.5
Top Layer: signal copper 0.035
Dielectric 1: prepreg 0.074, Dk 4.5
Signal Layer 1: signal copper 0.035
Dielectric 2: core 0.074, Dk 4.5
Signal Layer 2: signal copper 0.035
Dielectric 3: prepreg 0.18, Dk 4.5
Signal Layer 3: signal copper 0.035
Dielectric 4: core 0.6, Dk 4.5
Signal Layer 4: signal copper 0.035
Dielectric 5: prepreg 0.18, Dk 4.5
Signal Layer 5: signal copper 0.035
Dielectric 6: core 0.074, Dk 4.5
Signal Layer 6: signal copper 0.035
Dielectric 7: prepreg 0.074, Dk 4.5
Bottom Layer: signal copper 0.035
Bottom Solder: solder mask 0.0102, Solder Resist, Dk 3.5

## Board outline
0,0 12.239,0 12.239,5.25 cw(c12.745,5.25) 12.745,5.756 cw(c12.745,5.25) 13.25,5.25 13.25,0 31,0 31,41 26.15,41 26.15,38.4 24.607,38.4 24.607,41 19.95,41 19.95,38.4 18.394,38.4 18.394,41 13.25,41 13.25,23.3 cw(c12.744,23.3) 12.744,22.794 cw(c12.744,23.3) 12.239,23.3 12.239,41 0,41
cut-out: 12.251,10.578 ccw(c12.751,10.578) 12.751,10.078 ccw(c12.751,10.578) 13.251,10.578 13.25,10.6 13.25,17.9 ccw(c12.75,17.9) 12.75,18.4 ccw(c12.75,17.9) 12.25,17.9

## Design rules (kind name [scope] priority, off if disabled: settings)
Clearance Clearance_J2 [(ObjectKind = 'Pad') And (Name = 'J2-1') vs InPolygon] p1: gap=0.3 ignorepadtopadclearanceinfootprint=FALSE
Clearance "Clearance_Separation carte" [WithinRoom('Room_Separation carte')] p2: gap=0.11 ignorepadtopadclearanceinfootprint=FALSE except(0.14: Via-Fill Fill-Hole; 0.15: SMDPad-SMDPad SMDPad-Hole THPad-Hole Via-Via Via-Text Via-Hole Fill-Fill Fill-Poly Fill-Region Fill-Text Poly-Poly Poly-Region Poly-Text Poly-Hole Region-Region Region-Text Region-Hole Text-Hole; 0.18: SMDPad-THPad SMDPad-Via SMDPad-Fill SMDPad-Poly SMDPad-Region SMDPad-Text; 0.2: THPad-THPad THPad-Via THPad-Fill THPad-Poly THPad-Region THPad-Text Via-Poly Via-Region Text-Text)
Clearance Clearance_uVia [IsVia and (DrillPair = 'INN1-PWR - INN2-GND-PWR') vs IsVia] p3 off: gap=0 ignorepadtopadclearanceinfootprint=FALSE
Clearance Clearance_Same [IsVia vs IsVia] p4: gap=0 ignorepadtopadclearanceinfootprint=FALSE
Clearance Clearance_Keepout [IsKeepOut] p5: gap=0.001 ignorepadtopadclearanceinfootprint=FALSE
Clearance [All] p6: gap=0.15 ignorepadtopadclearanceinfootprint=FALSE except(0.18: Arc-SMDPad Track-SMDPad SMDPad-THPad SMDPad-Via SMDPad-Fill SMDPad-Poly SMDPad-Text Via-Region; 0.2: Arc-THPad Track-THPad THPad-THPad THPad-Via THPad-Fill THPad-Poly THPad-Region THPad-Text Via-Fill Via-Poly Text-Text)
ComponentClearance [All] p1: gap=0 collisioncheckmode=3 verticalgap=0 showdistances=FALSE
HoleToHoleClearance [All] p1: gap=0.15 allowstackedmicrovias=TRUE
MinimumSolderMaskSliver [All] p1: minsoldermaskwidth=0.1
PolygonConnect PolygonConnect_J2-3 [(ObjectKind = 'Pad') And (Name = 'J2-3')] p1: connectstyle=Relief reliefconductorwidth=0.2 reliefentries=4 polygonreliefangle="90 Angle" airgapwidth=0.226
PolygonConnect PolygonConnect_J2 [InComponent('J2')] p2: connectstyle=Relief reliefconductorwidth=0.2 reliefentries=4 polygonreliefangle="90 Angle" airgapwidth=0.227
PolygonConnect PolygonConnect_R2 [InComponent('R2')] p3: connectstyle=Relief reliefconductorwidth=0.2 reliefentries=4 polygonreliefangle="90 Angle" airgapwidth=0.23
PolygonConnect PolygonConnect_noyé [InComponent('D20','C1', 'C56', 'C37', 'C39', 'C40', 'C34', 'C31', 'C32', 'C35', 'C38', 'C27', 'C28', 'C29', 'C30', 'C33', 'C36', 'J1','J8', 'U12', 'C57', 'C70', 'R42', 'C63', 'C64', 'R49', 'U14', 'C18', 'C19', 'R54', 'R55', 'R56', 'J1', 'J7', 'Q2', 'Q3', 'Q4', 'Q5', 'Q6', 'Q7', 'L2', 'J3', 'J4', 'J5', 'J6', 'D7', 'C41', 'C44', 'C45', 'U9', 'D6', 'D8', 'D9', 'U8')] p4: connectstyle=Direct reliefconductorwidth=0.254 reliefentries=4 polygonreliefangle="90 Angle" airgapwidth=0.254
PolygonConnect [All] p5: thpad.connectstyle=Relief thpad.reliefconductorwidth=0.254 thpad.reliefentries=4 thpad.polygonreliefangle="90 Angle" thpad.airgapwidth=0.254 smdpad.connectstyle=Relief smdpad.reliefconductorwidth=0.2 smdpad.reliefentries=4 smdpad.polygonreliefangle="90 Angle" smdpad.airgapwidth=0.127 via.connectstyle=Direct via.reliefconductorwidth=0.254 via.reliefentries=4 via.polygonreliefangle="90 Angle" via.airgapwidth=0.254
RoomDefinition "Room_Separation carte" [False] p1: confinementstyle=ConfineIn formatcopy=TRUE lockcomponents=FALSE outline 12.24,23.462 13.25,23.462 13.25,5.11 12.24,5.11
RoutingVias [All] p1: holewidth=0.3 width=0.3 viastyle="Through Hole" minholewidth=0.1 minwidth=0.22 maxholewidth=0.5 maxwidth=0.7
ShortCircuit ShortCircuit_JP1-JP3 [InComponent('JP1', 'JP2', 'JP3') vs InComponent('JP1', 'JP2', 'JP3')] p1: allowed=TRUE
ShortCircuit [All] p2: allowed=FALSE
SolderMaskExpansion SolderMaskExpansion_Via [IsVia] p1: expansion=-10 istentingtop=FALSE
SolderMaskExpansion [All] p2: expansion=0.038 istentingtop=FALSE
Width [All] p1: maxlimit=5 minlimit=0.15 preferedwidth=0.2
26 further rules are at their usual default settings.

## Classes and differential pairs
component class SENSING: C66 C67 C68 C69 C70 D10 D11 D12 D13 D14 D15 D16 D17 D18 D19 J8 R57 R58 R59 R60 R61 R62 R63 R64 R65 R66 R67 R68 R69 R70 R71 R72 R73 R74 R75 R76 R77 R80 R81 R82 RT1
component class "POWER STAGE": C27 C28 C29 C30 C31 C32 C33 C34 C35 C36 C37 C38 C39 C40 C41 C42 C43 C44 C45 C46 C47 C48 C49 C50 C51 C52 C53 C54 C55 C56 C57 C58 C59 C60 C61 C62 C63 C64 C65 D6 D7 D8 D9 D20 J5 J6 J7 JP1 JP2 JP3 L2 Q2 Q3 Q4 Q5 Q6 Q7 R30 R31 R32 R33 R34 R35 R36 R37 R38 R39 R40 R41 R42 R43 R44 R45 R46 R47 R48 R49 R50 R51 R52 R53 R54 R55 R56 U9 U10 U11 U12 U13 U14
component class MCU: C18 C19 C20 C21 C22 C23 C24 C25 C26 D4 D5 J3 J4 L1 R26 R27 R28 R29 TP2 TP3 U8 Y2
component class DAUGHTERBOARD: C3 C4 C5 C6 C7 C8 C9 C10 C11 C12 C13 C14 C15 C16 C17 D2 D3 J2 Q1 R2 R3 R4 R5 R6 R7 R8 R9 R10 R11 R12 R13 R14 R15 R16 R17 R18 R19 R20 R21 R22 R23 R24 SW1 TP1 U3 U4 U5 U6 U7 Y1
component class CAN: C1 C2 D1 F1 J1 R1 U1 U2

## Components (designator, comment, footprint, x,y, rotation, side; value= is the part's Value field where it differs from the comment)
C1 "0.1uF" C_0402 27.85,13.57 r270 bottom
C2 "0.1uF" C_0402 28.55,19.9 r180 bottom
C3 "0.1uF" C_0402 0.65,15.4 r90 top
C4 "0.1uF" C_0402 8.61,12.22 r180 top
C5 "0.1uF" C_0402 5.3,16.7 r0 bottom
C6 "10uF" C_0805 8.55,16.6 r0 bottom
C7 "4.7uF" C_0805 5.85,8.4 r0 bottom
C8 "100pF" C_0402 1.75,22.4 r0 top
C9 "0.1uF" C_0402 9.2,11.3 r0 bottom
C10 "10pF" C_0402 7.55,27.9 r180 top
C11 "10pF" C_0402 9.6,27.9 r0 top
C12 "N.M." C_0402 1.79,11.72 r270 top
C13 "0.1uF" C_0402 5.65,24.1 r90 top
C14 "1 uF" C_0603 9.65,2.7 r270 bottom
C15 "0.1uF" C_0603 11.05,2.7 r270 bottom
C16 "1 uF" C_0603 3.65,2.6 r270 bottom
C17 "0.1uF" C_0402 4.85,3.1 r270 bottom
C18 "0.1uF" C_0402 19.45,13 r270 bottom
C19 "4.7uF" C_0603 18.35,13.5 r90 bottom
C20 "0.1uF" C_0402 26.6,15.5 r270 bottom
C21 "0.1uF" C_0402 16.65,19.3 r180 bottom
C22 "0.1uF" C_0402 27,21.25 r0 bottom
C23 "0.1uF" C_0402 14.4,19.8 r270 bottom
C24 "0.1uF" C_0402 25.3,23.75 r90 bottom
C25 "1uF" C_0402 23.9,23.33 r0 bottom
C26 "10nf" C_0402 23.9,24.2 r0 bottom
C27 "15uF" C_0805_HD 23.76,1.55 r90 bottom
C28 "15uF" C_0805_HD 25.411,4.5 r270 bottom
C29 "15uF" C_0805_HD 25.42,1.55 r90 bottom
C30 "15uF" C_0805_HD 18.78,1.55 r90 bottom
C31 "15uF" C_0805_HD 18.771,4.5 r270 bottom
C32 "15uF" C_0805_HD 20.431,4.5 r270 bottom
C33 "15uF" C_0805_HD 27.08,1.55 r90 bottom
C34 "15uF" C_0805_HD 17.12,1.55 r90 bottom
C35 "15uF" C_0805_HD 22.091,4.5 r270 bottom
C36 "15uF" C_0805_HD 23.751,4.5 r270 bottom
C37 "15uF" C_0805_HD 20.44,1.55 r90 bottom
C38 "15uF" C_0805_HD 22.091,1.55 r90 bottom
C39 "15uF" C_0805_HD 27.08,4.5 r270 bottom
C40 "15uF" C_0805_HD 17.12,4.5 r270 bottom
C41 "0.22uF" C_0603_HD 25.75,5.9 r270 top
C42 "3.9nf" C_0402 27.13,2.85 r90 top
C43 "1uF" C_0603_HD 15.75,20.5 r0 top
C44 "10uF" C_1206 27.35,7 r90 top
C45 "22uF" C_1206 19.05,2.8 r180 top
C46 "27pF" C_0402 22.2,2.2 r180 top
C47 "100pF" C_0402 14.55,11.8 r270 top
C48 "100pF" C_0402 15.85,12 r180 top
C49 "470nF" C_0603_HD 17.95,12.1 r0 top
C50 "4.7nF" C_0402 22.2,3.1 r180 top
C51 "10nf" C_0603 16.35,35.4 r0 bottom
C52 "1uF" C_0603_HD 21.4,20.5 r0 top
C53 "100pF" C_0402 20.2,11.8 r270 top
C54 "100pF" C_0402 21.5,12 r180 top
C55 "470nF" C_0603_HD 23.6,12.1 r0 top
C56 "1uF" C_0402 20.15,10.2 r90 bottom
C57 "2.2uF" C_0402 15.15,7.4 r270 bottom
C58 "1uF" C_0603_HD 27.05,20.5 r0 top
C59 "10nf" C_0603 22,35.4 r0 bottom
C60 "100pF" C_0402 25.85,11.8 r270 top
C61 "100pF" C_0402 27.15,12 r180 top
C62 "470nF" C_0603_HD 29.25,12.1 r0 top
C63 "1uF" C_0402 15.3,9.8 r0 bottom
C64 "2.2uF" C_0402 13.95,11.5 r270 bottom
C65 "10nf" C_0603 27.65,35.4 r0 bottom
C66 "10nf" C_0402 28.4,21.25 r90 bottom
C67 "10pF" C_0402 23.45,13 r0 bottom
C68 "10pF" C_0402 21.6,13.35 r270 bottom
C69 "10pF" C_0402 20.35,13.35 r270 bottom
C70 "0.1uF" C_0402 16.1,7.4 r270 bottom
CART-8L-1 "Comment" Sheetbox_8L2S -28.675,-25.65 r0 top
D1 "STPS1L20MF" do216-aa-flat 27.65,9.3 r90 bottom
D2 "LED GREEN RED" Led_bicolor_3528-PLCC-4 3.95,9.1 r0 top
D3 "LNJ347W83RA" D_0402_Led_green 10.85,5.8 r0 top
D4 "LED RED" D_0402_Led_red 29.8,7.75 r0 top
D5 "LNJ347W83RA" D_0402_Led_green 29.8,6.55 r0 top
D6 "STPS0560Z" SOD_123 16.95,10.4 r0 top
D7 "STPS1L40M" do216-aa_stmite 23.85,8.1 r0 top
D8 "STPS0560Z" SOD_123 22.6,10.4 r0 top
D9 "STPS0560Z" SOD_123 28.25,10.4 r0 top
D10 "BAT30KFILM" sodfl160x80x65l30x30n 16.7,24.9 r270 bottom
D11 "BAT30KFILM" sodfl160x80x65l30x30n 15.55,24.9 r270 bottom
D12 "BAT30KFILM" sodfl160x80x65l30x30n 18.45,25.85 r0 bottom
D13 "BAT30KFILM" sodfl160x80x65l30x30n 21.3,25 r270 bottom
D14 "BAT30KFILM" sodfl160x80x65l30x30n 29.75,22.75 r180 bottom
D15 "BAT30KFILM" sodfl160x80x65l30x30n 29.75,23.95 r180 bottom
D16 "BAT30KFILM" sodfl160x80x65l30x30n 14.27,22.1 r270 bottom
D17 "BAT30KFILM" sodfl160x80x65l30x30n 25.1,11.1 r90 bottom
D18 "BAT30KFILM" sodfl160x80x65l30x30n 22.99,11.1 r90 bottom
D19 "BAT30KFILM" sodfl160x80x65l30x30n 21.2,11.7 r0 bottom
D20 "SMM4F26A" do216-aa-flat 29.35,3.45 r270 bottom
F1 "250mA" f_0402 29.4,7.25 r0 bottom
J1 "can" SOLDER_PAD_4PIN_SMD 29.87,8.67 r90 bottom
J2 "SWD STLINK" strip4_100m_v 1.05,6.14 r270 top
J3 "PWM" SOLDER_PAD_5PIN_SMD 17.9,0.85 r0 top
J4 "SWD-PAD" SOLDER_PAD_4PIN_rect_SMD 14.35,9.05 r270 top
J5 "CON1" wire1_220s 29.4,2.1 r0 top
J6 "CON1" wire1_220s 14.95,2.1 r0 top
J7 "Motor" conn_motor_out 22.25,39.65 r180 top
J8 "SOLDER PAD" SOLDER_PAD_5PIN_SMD 25.2,7.75 r180 bottom
JP1 "Short" SHORT 16.35,29.65 r0 top
JP2 "Short" SHORT 22,29.65 r0 top
JP3 "Short" SHORT 27.65,29.65 r0 top
L1 "600 Ohms@100MHz" L_0402 26.4,25.35 r0 bottom
L2 "33uH" ind_Coilcraft-LPS4018 18.9,6.65 r180 top
Q1 "2STR1160" sot23-3p97_255x140l40x40n 9.47,8.68 r180 top
Q2 "STL180N6F7" power_flat_5x6 16.55,26.1 r180 top
Q3 "STL180N6F7" power_flat_5x6 16.55,34.5 r0 top
Q4 "STL180N6F7" power_flat_5x6 22.2,26.1 r180 top
Q5 "STL180N6F7" power_flat_5x6 22.2,34.5 r0 top
Q6 "STL180N6F7" power_flat_5x6 27.85,26.1 r180 top
Q7 "STL180N6F7" power_flat_5x6 27.85,34.5 r0 top
R1 "120" R_0402 26.8,12.2 r0 bottom
R2 "10K" trimmer-3386P_T 6.25,35.8 r180 top
R3 "10K" R_0402 10.09,11.18 r180 top
R4 "100" R_0402 11.31,13.58 r270 top
R5 "1.5k" R_0402 8.08,7.1 r180 top
R6 "36K" R_0402 10.37,13.54 r270 top
R7 "100K" R_0402 8.6,5.9 r180 top
R8 "470" R_0402 6.23,11.72 r270 top
R9 "470" R_0402 5.35,11.72 r90 top
R10 "10K" R_0402 1.35,21.4 r180 top
R11 "0" R_0402 5.85,6.82 r180 top
R12 "10K" R_0402 3.95,10.95 r90 bottom
R13 "100K" R_0402 11.55,19.3 r90 top
R14 "2.7K" R_0402 9.2,12.2 r0 bottom
R15 "100K" R_0402 5.65,25.9 r270 top
R16 "10K" R_0402 10.45,22.6 r0 top
R17 "N.M." R_0402 10.45,23.5 r0 top
R18 "100" R_0402 3.05,11.24 r0 top
R19 "4.7K" R_0402 4.45,25.9 r90 top
R20 "100" R_0402 3.05,12.35 r0 top
R21 "1K" R_0402 10.95,6.8 r0 top
R22 "4.7K" R_0402 4.45,24.1 r90 top
R23 "0" JUMPER_0603_DROP 3.15,16.65 r90 bottom
R24 "0" JUMPER_0603_DROP 1.45,16.65 r90 bottom
R26 "0" R_0402 17.35,16.15 r270 bottom
R27 "220" R_0402 16.95,17.9 r0 bottom
R28 "510" R_0402 29.85,8.75 r0 top
R29 "510" R_0402 29.85,5.55 r0 top
R30 "4.7K" R_0402 25.8,3.25 r180 top
R31 "62" R_0402 25.8,2.35 r180 top
R32 "34.8k" R_0402 26.15,4.3 r0 top
R33 "300" R_0402 24.45,2.6 r270 top
R34 "33" R_0603_HD 14.95,21.7 r180 top
R35 "10K" R_0402 14.05,29.2 r90 bottom
R36 "8.2k" R_0402 23.55,2.6 r270 top
R37 "1" R_0805 16.55,37 r0 bottom
R38 "33" R_0603_HD 18.35,21.2 r90 top
R39 "10K" R_0402 18.35,30.4 r180 top
R40 "33" R_0603_HD 20.6,21.7 r180 top
R41 "10K" R_0402 19.7,29.2 r90 bottom
R42 "52.3k" R_0402 15.25,8.85 r180 bottom
R43 "33" R_0603_HD 24,21.2 r90 top
R44 "1" R_0805 22.2,37 r0 bottom
R45 "10K" R_0402 24,30.4 r180 top
R46 "10K" R_0402 17.8,11.65 r0 bottom
R47 "33" R_0603_HD 26.205,21.7 r180 top
R48 "10K" R_0402 25.35,29.2 r90 bottom
R49 "30.9k" R_0402 13.95,13.5 r270 bottom
R50 "33" R_0603_HD 29.655,21.195 r90 top
R51 "1" R_0805 27.85,37 r0 bottom
R52 "10K" R_0402 29.65,30.4 r180 top
R53 "10K" R_0402 16.2,13.85 r0 bottom
R54 "0.003" resc635x300x60l193n 16.55,30.5 r270 bottom
R55 "0.003" resc635x300x60l193n 22.2,30.5 r270 bottom
R56 "0.003" resc635x300x60l193n 27.85,30.5 r270 bottom
R57 "2.2k" R_0402 16.65,23.2 r180 bottom
R58 "2.2k" R_0402 20.9,23.35 r0 bottom
R59 "2.2k" R_0402 28.14,23.25 r90 bottom
R60 "4.7K" R_0402 29.35,21.25 r90 bottom
R61 "10K" R_0603_HD 14.3,24.85 r270 bottom
R62 "10K" R_0603_HD 20.15,24.95 r270 bottom
R63 "10K" R_0603 27,23.1 r270 bottom
R64 "22k" r_0402 16.65,22.25 r180 bottom
R65 "22k" r_0402 18.3,23.95 r180 bottom
R66 "22k" r_0402 22.75,25.48 r180 bottom
R67 "1.5k" R_0402 16.65,20.45 r180 bottom
R68 "169k" R_0402 15.3,21.75 r270 bottom
R69 "1.5k" R_0402 18.3,24.85 r180 bottom
R70 "1.5k" R_0402 22.25,23.8 r90 bottom
R71 "10K" R_0402 24.95,13.2 r270 bottom
R72 "10K" R_0402 24.01,11.2 r90 bottom
R73 "10K" R_0402 21.5,10.68 r180 bottom
R74 "1.8k" R_0402 25.25,9.3 r0 bottom
R75 "1.8k" R_0402 23.45,9.3 r0 bottom
R76 "18k" R_0402 15.3,19.8 r270 bottom
R77 "1.8k" R_0402 21.55,9.7 r180 bottom
R80 "2.2k" R_0402 16.65,21.35 r0 bottom
R81 "2.2k" R_0402 18.65,23.05 r0 bottom
R82 "2.2k" R_0402 24.55,25.5 r180 bottom
RT1 "10K" R_0402 28.2,25.9 r0 bottom
SW1 "miniswitch-KMR211GLFS" switch_SMT_4_2x2_8mm 1.85,25.64 r270 top
TP1 "TP" test_point_100_smd 0.85,11.1 r180 top
TP2 "TP" test_point_100_smd 23.1,14 r90 bottom
TP3 "TP" test_point_100_smd 28.2,24.7 r0 bottom
U1 "AS11P2TLRQ" son6p40_120x100x55l35x20 26.4,13.65 r270 bottom
U2 "TCAN330DCNT" sot23-8p65_280x145l45x30n 28.45,17.5 r0 bottom
U3 "LD1117S50TR" sot223-4p230_700x190l65x72 7.55,21.8 r0 bottom
U4 "conn_micro_USB_B" conn_micro_USB_B_SMD 7.41,1.76 r90 top
U5 "ST890DTR" son9p65_300x300x90l30x30t240-1 6.35,11.24 r90 bottom
U6 "STM32F103CBT6" qfp48p50_900x900x160l60x22n 6.13,17.86 r180 top
U7 "LD39050PU33R" son7p95_300x300x100l40x34t23-1 7.15,2.4 r0 bottom
U8 "STM32G431" qfn49p50_700x700x60l40x25t560n 22.05,18.5 r90 bottom
U9 "L7986TR" son11p50_300x300x100l40x24t2-1 23.35,5.2 r270 top
U10 "L6387ED" SOIC8P127_490X600X175L83X42N 16.45,16.3 r0 top
U11 "L6387ED" SOIC8P127_490X600X175L83X42N 22.1,16.3 r0 top
U12 "LDFPVR" son7p65_200x200x100l25x30t18-1 18.25,10.1 r90 bottom
U13 "L6387ED" SOIC8P127_490X600X175L83X42N 27.75,16.3 r0 top
U14 "LDFPVR" son7p65_200x200x100l25x30t18-1 15.6,11.8 r0 bottom
Y1 "NX3225GD-8MHZ-STD-CRA-3" xtaldfn2_320x250x100l130x230 8.45,25.8 r180 top
Y2 "8Mhz" murata_cstce8m00g15c99-r0 14.75,16.6 r90 bottom

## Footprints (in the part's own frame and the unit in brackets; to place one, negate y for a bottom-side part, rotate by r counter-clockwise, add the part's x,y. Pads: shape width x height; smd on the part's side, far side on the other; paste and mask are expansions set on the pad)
C_0402 [mm] "C_0402"
  rrect52% 0.58x0.58 smd mask+0.05: 1(-0.46,0) 2(0.46,0)
  silkscreen extent 0,-0.25 0,0.25, body extent -0.5,-0.25 0.5,0.25, height 0.55
C_0603 [mm] "C_0603"
  rrect50% 0.84x0.93 smd mask+0.05: 1(-0.745,0) 2(0.745,0)
  silkscreen extent -0.15,-0.45 0.14,0.45, body extent -0.82,-0.41 0.78,0.4, height 0.9
C_0603_HD [mm] "C_0603_HD"
  rrect51% 0.74x0.83 smd mask+0.05: 1(-0.695,0) 2(0.695,0)
  silkscreen extent -0.18,-0.45 0.17,0.45, body extent -0.8,-0.41 0.8,0.41, height 0.9
C_0805 [mm] "C_0805"
  rrect48% 1.05x1.48 smd mask+0.05: 1(-0.94,0) 2(0.94,0)
  silkscreen extent -0.23,-0.73 0.24,0.73, body extent -1,-0.63 1,0.63, height 1.4
C_0805_HD [mm] "C_0805_HD"
  rrect51% 0.95x1.38 smd mask+0.05: 1(-0.89,0) 2(0.89,0)
  silkscreen extent -0.26,-0.73 0.27,0.73, body extent -1,-0.63 1,0.63, height 1.4
C_1206 [mm] "C_1206"
  rrect50% 1x1.77 smd mask+0.05: 1(-1.535,0) 2(1.535,0)
  silkscreen extent -0.85,-0.88 0.85,0.88, body extent -1.6,-0.8 1.6,0.8, height 1.27
conn_micro_USB_B_SMD [mm] "CONN_MICRO_USB_B_SMD"
  rect 1.37x0.45 smd mask+0.05: 1(2.314,1.299) 2(2.314,0.649) 3(2.314,0) 4(2.314,-0.65) 5(2.314,-1.3)
  rect 2.11x1.47 smd mask+0.05: 6(1.946,2.463) 7(1.946,-2.463)
  rect 1.9x2.36 smd mask+0.05: 8(-0.35,2.919) 9(-0.35,-2.919)
  Top Layer region: -1.3,-1.425 0.6,-1.425 0.6,-0.25 -1.3,-0.25
  Top Layer region: -1.3,0.25 0.6,0.25 0.6,1.425 -1.3,1.425
  silkscreen extent 0.9,-3.75 3.4,3.75, body extent -2.81,-3.99 2.62,3.99, height 2.72
conn_motor_out [mm] "CONN_MOTOR_OUT"
  rect 4.5x2.5 / inner round 0.56 / far side rect 4.5x2.5 hole 0.254: 1(-6.2,0) 2(0,0) 3(6.2,0)
D_0402_Led_green [mm] "D_0402_LED_GREEN"
  rrect51% 0.7x0.7 smd mask+0.05: A(0.525,0) C(-0.525,0)
  silkscreen extent -1.39,-0.53 1.06,0.53, body extent -0.5,-0.3 0.5,0.3, height 0.08
D_0402_Led_red [mm] "D_0402_LED_RED"
  rrect51% 0.7x0.7 smd mask+0.05: A(0.525,0) C(-0.525,0)
  silkscreen extent -1.39,-0.53 1.06,0.53, body extent -0.5,-0.25 0.5,0.25, height 0.32
do216-aa-flat [mm] "DO216-AA-FLAT"
  rect 0.85x0.65 smd mask+0.05: A(-1.599,0)
  oct 0.025x0.025 smd: C(0.781,0)
  Top Layer region: -0.544,0.975 1.456,0.975 1.456,0.475 2.106,0.475 2.106,-0.475 1.456,-0.475 1.456,-0.975 -0.544,-0.975 -0.544,0.975
  silkscreen extent -1.51,-1 2.34,1, body extent -1.86,-0.95 1.94,0.95, height 0.85
do216-aa_stmite [mm] "DO216-AA_STMITE"
  rect 1.38x0.75 smd mask+0.05: A(1.555,0)
  rect 2.32x2.03 smd mask+0.05: C(-1.015,0)
  silkscreen extent -2.4,-1 0.5,1, body extent -2,-0.99 1.85,1.01, height 1.01
f_0402 [mm] "F_0402"
  rrect52% 0.58x0.58 smd mask+0.05: 1(0.46,0) 2(-0.46,0)
  silkscreen extent 0,-0.25 0,0.25, body extent -0.49,-0.25 0.5,0.25, height 0.38
ind_Coilcraft-LPS4018 [mm] "IND_COILCRAFT-LPS4018"
  rect 1.45x3.89 smd mask+0.05: 1(-1.475,0) 2(1.475,0)
  silkscreen extent -0.57,-1.99 0.57,1.99, body extent -1.99,-1.99 1.99,1.99, height 1.8
JUMPER_0603_DROP [mil] "JUMPER_0603_DROP"
  oct 1x1 smd: 1(-22.26,0) 2(22.45,0)
  Top Layer region: -46.87,-18.12 1.95,-18.12 -16.16,-0.01 1.95,18.1 -46.87,18.1 -46.87,-18.12
  Top Layer region: 46.66,-18.12 15.95,-18.12 -2.16,-0.01 15.95,18.1 46.66,18.1 46.66,-18.12
  silkscreen extent -59,-30 59,30, body extent -31,-17 31,17, height 20
L_0402 [mm] "L_0402"
  rrect52% 0.58x0.58 smd mask+0.05: 1(0.46,0) 2(-0.46,0)
  silkscreen extent 0,-0.25 0,0.25, body extent -0.5,-0.25 0.5,0.25, height 0.55
Led_bicolor_3528-PLCC-4 [mm] "LED_BICOLOR_3528-PLCC-4"
  rect 1.5x1.1 smd mask+0.05: A1(1.5,0.75) A2(1.5,-0.753) C1(-1.5,0.75) C2(-1.5,-0.753)
  silkscreen extent -2.46,-1.48 1.64,1.48, body extent -1.75,-1.4 1.75,1.4, height 1.91
murata_cstce8m00g15c99-r0 [mm] "MURATA_CSTCE8M00G15C99-R0"
  rect 0.4x2 smd mask+0.05: 1(-1.2,0) 2(0,0) 3(1.2,0)
  silkscreen extent -2.1,-0.65 1.6,0.65, body extent -1.6,-0.65 1.6,0.65, height 0.7
power_flat_5x6 [mm] "POWER_FLAT_5X6"
  rect 0.71x1.35 smd mask+0.05: 1(-1.905,-2.665) 2(-0.635,-2.665) 3(0.635,-2.665) 4(1.905,-2.665) 5(1.905,2.665) 6(0.635,2.665) 7(-0.635,2.665) 8(-1.905,2.665)
  Top Layer region: 2.3,-1.13 2.3,2.77 -2.3,2.77 -2.3,-1.13 2.3,-1.13
  silkscreen extent -2.6,-3.6 2.6,3.6, body extent -2.61,-3.1 2.59,3.05, height 0.98
qfn49p50_700x700x60l40x25t560n [mm] "QFN49P50_700X700X60L40X25T560N"
  rrect52% 0.27x0.76 smd mask+0.05: 1(-2.75,-3.385) 2(-2.25,-3.385) 3(-1.75,-3.385) 4(-1.25,-3.385) 5(-0.75,-3.385) 6(-0.25,-3.385) 7(0.25,-3.385) 8(0.75,-3.385) 9(1.25,-3.385) 10(1.75,-3.385) 11(2.25,-3.385) 12(2.75,-3.385) 25(2.75,3.385) 26(2.25,3.385) 27(1.75,3.385) 28(1.25,3.385) 29(0.75,3.385) 30(0.25,3.385) 31(-0.25,3.385) 32(-0.75,3.385) 33(-1.25,3.385) 34(-1.75,3.385) 35(-2.25,3.385) 36(-2.75,3.385)
  rrect52% 0.76x0.27 smd mask+0.05: 13(3.385,-2.75) 14(3.385,-2.25) 15(3.385,-1.75) 16(3.385,-1.25) 17(3.385,-0.75) 18(3.385,-0.25) 19(3.385,0.25) 20(3.385,0.75) 21(3.385,1.25) 22(3.385,1.75) 23(3.385,2.25) 24(3.385,2.75) 37(-3.385,2.75) 38(-3.385,2.25) 39(-3.385,1.75) 40(-3.385,1.25) 41(-3.385,0.75) 42(-3.385,0.25) 43(-3.385,-0.25) 44(-3.385,-0.75) 45(-3.385,-1.25) 46(-3.385,-1.75) 47(-3.385,-2.25) 48(-3.385,-2.75)
  oct 0.025x0.025 smd mask+0.05: 49(0,0)
  Top Layer region: -2.8,2.8 -2.8,-2.3 -2.3,-2.8 2.8,-2.8 2.8,2.8 -2.8,2.8
  silkscreen extent -3.55,-3.74 3.55,3.55, body extent -3.51,-3.51 3.51,3.51, height 0.78
qfp48p50_900x900x160l60x22n [mm] "QFP48P50_900X900X160L60X22N"
  rrect53% 0.3x1.26 smd mask+0.05: 1(-2.75,-4.13) 2(-2.25,-4.13) 3(-1.75,-4.13) 4(-1.25,-4.13) 5(-0.75,-4.13) 6(-0.25,-4.13) 7(0.25,-4.13) 8(0.75,-4.13) 9(1.25,-4.13) 10(1.75,-4.13) 11(2.25,-4.13) 12(2.75,-4.13) 25(2.75,4.13) 26(2.25,4.13) 27(1.75,4.13) 28(1.25,4.13) 29(0.75,4.13) 30(0.25,4.13) 31(-0.25,4.13) 32(-0.75,4.13) 33(-1.25,4.13) 34(-1.75,4.13) 35(-2.25,4.13) 36(-2.75,4.13)
  rrect53% 1.26x0.3 smd mask+0.05: 13(4.13,-2.75) 14(4.13,-2.25) 15(4.13,-1.75) 16(4.13,-1.25) 17(4.13,-0.75) 18(4.13,-0.25) 19(4.13,0.25) 20(4.13,0.75) 21(4.13,1.25) 22(4.13,1.75) 23(4.13,2.25) 24(4.13,2.75) 37(-4.13,2.75) 38(-4.13,2.25) 39(-4.13,1.75) 40(-4.13,1.25) 41(-4.13,0.75) 42(-4.13,0.25) 43(-4.13,-0.25) 44(-4.13,-0.75) 45(-4.13,-1.25) 46(-4.13,-1.75) 47(-4.13,-2.25) 48(-4.13,-2.75)
  silkscreen extent -3.6,-4.64 3.6,3.6, body extent -4.5,-4.5 4.5,4.5, height 1.45
R_0402 [mm] "R_0402"
  rrect52% 0.58x0.58 smd mask+0.05: 1(-0.46,0) 2(0.46,0)
  silkscreen extent 0,-0.25 0,0.25, body extent -0.5,-0.25 0.5,0.25, height 0.4
r_0402 [mm] "R_0402"
  rrect52% 0.58x0.58 smd mask+0.05: 1(-0.46,0) 2(0.46,0)
  silkscreen extent 0,-0.25 0,0.25, body extent -0.5,-0.25 0.5,0.25, height 0.4
R_0603 [mm] "R_0603"
  rrect50% 0.84x0.93 smd mask+0.05: 1(-0.745,0) 2(0.745,0)
  silkscreen extent -0.15,-0.45 0.14,0.45, body extent -0.79,-0.43 0.79,0.42, height 0.5
R_0603_HD [mm] "R_0603_HD"
  rrect50% 0.72x0.83 smd mask+0.05: 1(-0.705,0) 2(0.705,0)
  silkscreen extent -0.19,-0.45 0.2,0.45, body extent -0.79,-0.43 0.79,0.43, height 0.5
R_0805 [mm] "R_0805"
  rrect49% 0.81x1.38 smd mask+0.05: 1(0.96,0) 2(-0.96,0)
  silkscreen extent -0.38,-0.68 0.38,0.68, body extent -1,-0.63 1,0.63, height 0.7
resc635x300x60l193n [mm] "RESC635X300X60L193N"
  rrect18% 2.78x3.22 smd mask+0.05: 1(-2.415,0) 2(2.415,0)
  silkscreen extent -0.84,-1.6 0.84,1.6, body extent -3.15,-1.58 3.15,1.58, height 0.7
Sheetbox_8L2S [mil] "Sheetbox 8 layers / 2 silkscreens"
  round 20 on Mech16: 1(813.5,208.05) 1(2736.63,208.05)
SHORT [mm] "SHORT"
  rect 0.462x0.2 on Mid4: 1(-0.226,0) 2(0.201,0)
SOD_123 [mm] "SOD_123"
  rrect51% 1.08x0.86 smd mask+0.05: A(1.69,0) C(-1.69,0)
  silkscreen extent -2.43,-0.9 1.42,0.9, body extent -1.85,-0.8 1.85,0.8, height 1.27
sodfl160x80x65l30x30n [mm] "SODFL160X80X65L30X30N"
  rrect50% 0.64x0.4 smd mask+0.05: A(0.73,0) C(-0.73,0)
  silkscreen extent -1.23,-0.43 0.63,0.43, body extent -0.8,-0.4 0.8,0.4, height 0.65
SOIC8P127_490X600X175L83X42N [mm] "SOIC8P127_490X600X175L83X42N"
  rrect52% 0.66x2.07 smd mask+0.05: 1(-1.905,-2.425) 2(-0.635,-2.425) 3(0.635,-2.425) 4(1.905,-2.425) 5(1.905,2.425) 6(0.635,2.425) 7(-0.635,2.425) 8(-1.905,2.425)
  silkscreen extent -2.5,-3.41 2.5,2, body extent -2.45,-3 2.45,3, height 1.75
SOLDER_PAD_4PIN_rect_SMD [mm] "SOLDER_PAD_4PIN_RECT_SMD"
  rect 0.85x1.5 smd paste-100 mask+0.05: 1(0,0) 2(1.35,0) 3(2.7,0) 4(4.05,0)
SOLDER_PAD_4PIN_SMD [mm] "SOLDER_PAD_4PIN_SMD"
  round 1.4 smd paste-100 mask+0.05: 1(0,0) 2(1.9,0) 3(3.8,0) 4(5.7,0)
SOLDER_PAD_5PIN_SMD [mm] "SOLDER_PAD_5PIN_SMD"
  round 1.4 smd paste-2.54 mask+0.05: 1(0,0) 2(1.9,0) 3(3.8,0) 4(5.7,0) 5(7.6,0)
son6p40_120x100x55l35x20 [mm] "SON6P40_120X100X55L35X20"
  rrect55% 0.22x0.69 smd mask+0.04: 1(-0.4,-0.405)
  rrect55% 0.22x0.66 smd mask+0.04: 2(0,-0.42) 3(0.4,-0.42) 4(0.4,0.42) 5(0,0.42) 6(-0.4,0.42)
  silkscreen extent -0.69,-0.69 0.69,0.53, body extent -0.6,-0.55 0.6,0.55, height 0.55
son7p65_200x200x100l25x30t18-1 [mm] "SON7P65_200X200X100L25X30T18-1"
  rrect50% 0.32x0.56 smd mask+0.05: 1(-0.65,-0.975) 2(0,-0.975) 3(0.65,-0.975) 4(0.65,0.975) 5(0,0.975) 6(-0.65,0.975)
  oct 0.025x0.025 smd paste-100 mask+0: 7(0,0)
  Top Layer region: -0.9,0.5 -0.9,-0.3 -0.7,-0.5 0.9,-0.5 0.9,0.5 -0.9,0.5
  silkscreen extent -1.08,-1.2 1.08,1, body extent -1,-1 1,1, height 0.75
son7p95_300x300x100l40x34t23-1 [mm] "SON7P95_300X300X100L40X34T23-1"
  rrect50% 0.4x0.75 smd mask+0.05: 1(0.95,1.39) 2(0,1.39) 3(-0.95,1.39) 4(-0.95,-1.39) 5(0,-1.39) 6(0.95,-1.39)
  rect 2.365x1.625 smd paste-100 mask+0.05: 7(0,0)
  silkscreen extent -1.55,-1.55 1.55,2.03, body extent -1.5,-1.55 1.5,1.55, height 0.75
son9p65_300x300x90l30x30t240-1 [mm] "SON9P65_300X300X90L30X30T240-1"
  rrect50% 0.32x0.61 smd mask+0.05: 1(-0.975,-1.445) 2(-0.325,-1.445) 3(0.325,-1.445) 4(0.975,-1.445) 5(0.975,1.445) 6(0.325,1.445) 7(-0.325,1.445) 8(-0.975,1.445)
  oct 0.025x0.025 smd paste-100 mask+0: 9(0,0)
  Top Layer region: -1.2,0.9 -1.2,-0.6 -0.9,-0.9 1.2,-0.9 1.2,0.9 -1.2,0.9
  silkscreen extent -1.53,-1.69 1.53,1.53, body extent -1.5,-1.55 1.5,1.55, height 1
son11p50_300x300x100l40x24t2-1 [mm] "SON11P50_300X300X100L40X24T2-1"
  rrect54% 0.26x0.73 smd mask+0.05: 1(-1,-1.385) 2(-0.5,-1.385) 3(0,-1.385) 4(0.5,-1.385) 5(1,-1.385) 6(1,1.385) 7(0.5,1.385) 8(0,1.385) 9(-0.5,1.385) 10(-1,1.385)
  oct 0.025x0.025 smd paste-100: 11(0,0)
  Top Layer region: 1.5,-0.82 1.5,0.82 -1.5,0.82 -1.5,-0.82 1.5,-0.82
  silkscreen extent -1.53,-2.09 1.53,1.53, body extent -1.5,-1.55 1.5,1.55, height 1
sot23-3p97_255x140l40x40n [mm] "SOT23-3P97_255X140L40X40N"
  rrect50% 0.64x1.38 smd mask+0.05: 1(-0.97,-1.165) 2(0.97,-1.165) 3(0,1.165)
  silkscreen extent -1.52,-0.88 1.52,0.88, body extent -1.45,-1.4 1.45,1.4, height 1.45
sot23-8p65_280x145l45x30n [mm] "SOT23-8P65_280X145L45X30N"
  rrect52% 0.46x1.11 smd mask+0.045: 1(-0.975,-1.205) 2(-0.325,-1.205) 3(0.325,-1.205) 4(0.975,-1.205) 5(0.975,1.205) 6(0.325,1.205) 7(-0.325,1.205) 8(-0.975,1.205)
  silkscreen extent -1.5,-1.7 1.5,0.88, body extent -1.47,-1.4 1.47,1.4, height 1.2
sot223-4p230_700x190l65x72 [mm] "SOT223-4P230_700X190L65X72"
  rrect51% 0.95x1.32 smd mask+0.05: 1(2.3,3.24) 2(0,3.24) 3(-2.3,3.24)
  rrect36% 3.25x1.32 smd mask+0.05: 4(0,-3.24)
  silkscreen extent -3.35,-1.85 3.35,3.84, body extent -3.25,-3.44 3.25,3.56, height 1.66
strip4_100m_v [mil] "STRIP4_100M_V"
  rect 70x70 hole 39 mask+3.94: 1(0,100)
  round 70 hole 39 mask+3.94: 2(0,0) 3(100,0) 4(200,0)
switch_SMT_4_2x2_8mm [mm] "SWITCH_SMT_4_2X2_8MM"
  rect 0.9x1 smd mask+0.05: 1(-2.056,0.805) 2(2.056,0.805) 3(-2.056,-0.805) 4(2.056,-0.805)
  rect 1.7x0.56 smd mask+0.05: " "(0,1.4)
  silkscreen extent -1.35,-1.4 1.35,1.4, body extent -2.31,-1.39 2.29,1.41, height 1.92
test_point_100_smd [mm] "TEST_POINT_100_SMD"
  round 1 smd paste-100 mask+0.05: 1(0,0)
trimmer-3386P_T [mm] "TRIMMER-3386P_T"
  round 1.2 hole 0.8 mask+0.1: 1(2.54,-0.015) 2(0,-2.555) 3(-2.54,-0.015)
  silkscreen extent -4.76,-4.76 4.76,4.76, body extent -4.8,-4.85 4.78,4.73, height 10.55
wire1_220s [mm] "WIRE1_220S"
  rect 3x4 smd paste-100 mask+0.05: 1(0,0)
xtaldfn2_320x250x100l130x230 [mm] "XTALDFN2_320X250X100L130X230"
  rect 1.5x2.7 smd mask+0.05: 1(-0.95,0) 2(0.95,0)
  silkscreen extent -1.9,-1.55 1.9,1.55, body extent -1.61,-1.25 1.59,1.25, height 1.01

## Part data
C1 C2 C3 C4 C5 C9 C17 C18 C20 C21 C22 C23 C24: library part CAP_Dup1, "CAP CER 0.1UF 16V X7R 0402", Dielectric Type=Capacitors, Manufacturer="Wurth Electronics Inc.", Manufacturer PN=885012205037, Package Size="0402 (1005 Metric)", Rated Voltage=16V, Temperature Coefficient=X7R, Tolerance=10%
C6: library part CAP_Dup1, "CAP CER 10UF 16V X5R 0805", Dielectric Type=Capacitors, Manufacturer="Wurth Electronics Inc.", Manufacturer PN=885012107014, Package Size="0805 (2012 Metric)", Rated Voltage=16V, Temperature Coefficient=X5R, Tolerance=20%
C7: library part CAP_Dup1, "CAP CER 4.7UF 16V X5R 0805", Dielectric Type=Capacitors, Manufacturer="Wurth Electronics Inc.", Manufacturer PN=885012107013, Package Size="0805 (2012 Metric)", Rated Voltage=16V, Temperature Coefficient=X5R, Tolerance=20%
C8: library part CAP_Dup1, "CAP CER 100PF 10V C0G/NP0 0402", Dielectric Type=Capacitors, Manufacturer="Wurth Electronics Inc.", Manufacturer PN=885012005013, Package Size="0402 (1005 Metric)", Rated Voltage=10V, Temperature Coefficient="C0G, NP0", Tolerance=5%
C10 C11: library part CAP_7, "CAP CER 10PF 10V C0G/NP0 0402", Dielectric Type=Capacitors, Manufacturer="Wurth Electronics Inc.", Manufacturer PN=885012005007, Package Size="0402 (1005 Metric)", Rated Voltage=10V, Temperature Coefficient="C0G, NP0", Tolerance=5%
C12: library part CAP_6, "CAP CER 0402-NOT MOUNTED", Package Size="0402 (1005 Metric)"
C13: library part CAP_8, "CAP CER 0.1UF 16V X7R 0402", Dielectric Type=Capacitors, Manufacturer="Wurth Electronics Inc.", Manufacturer PN=885012205037, Package Size="0402 (1005 Metric)", Rated Voltage=16V, Temperature Coefficient=X7R, Tolerance=10%
C14 C16: library part CAP_Dup1, "CAP CER 1UF 16V X5R 0603", Dielectric Type=Capacitors, Manufacturer=Yageo, Manufacturer PN=CC0603KRX5R7BB105, Package Size="0603 (1608 Metric)", Rated Voltage=16V, Temperature Coefficient=X5R, Tolerance=10%
C15: library part CAP_Dup1, "CAP CER 0.1UF 16V X7R 0603", Dielectric Type=Capacitors, Manufacturer="Wurth Electronics Inc.", Manufacturer PN=885012206046, Package Size="0603 (1608 Metric)", Rated Voltage=16V, Temperature Coefficient=X7R, Tolerance=10%
C19: library part CAP_Dup1, "CAP CER 4.7UF 10V X5R 0603", Dielectric Type=Capacitors, Manufacturer="Wurth Electronics Inc.", Manufacturer PN=885012106012, Package Size="0603 (1608 Metric)", Rated Voltage=10V, Temperature Coefficient=X5R, Tolerance=20%
C25 C56 C63: library part CAP_Dup1, "CAP CER 1UF 25V X5R 0402", Dielectric Type=Capacitors, Manufacturer="Murata Electronics North America", Manufacturer PN=GRM155R61E105KA12D, Package Size="0402 (1005 Metric)", Rated Voltage=25V, Temperature Coefficient=X5R, Tolerance=10%
C26: library part CAP_Dup1, "CAP CER 10000PF 16V X7R 0402", Dielectric Type=Capacitors, Manufacturer="Wurth Electronics Inc.", Manufacturer PN=885012205031, Package Size="0402 (1005 Metric)", Rated Voltage=16V, Temperature Coefficient=X7R, Tolerance=10%
C27 C28 C29 C30 C31 C32 C33 C34 C35 C36 C37 C38 C39 C40: library part CAP_Dup1, "CAP CER 15UF 35V X5R 0805", Dielectric Type=Capacitors, Manufacturer="TDK Corporation", Manufacturer PN=C2012X5R1V156M125AC, Package Size="0805 (2012 Metric)", Rated Voltage=35V, Temperature Coefficient=X5R, Tolerance=20%
C41: library part CAP_Dup1, "CAP CER 0.22UF 50V X7R 0603", Dielectric Type=Capacitors, Manufacturer="TDK Corporation", Manufacturer PN=CGA3E3X7R1H224K080AD, Package Size="0603 (1608 Metric)", Rated Voltage=50V, Temperature Coefficient=X7R, Tolerance=10%
C42: library part CAP_Dup1, "CAP CER 3900PF 16V X7R 0402", Dielectric Type=Capacitors, Manufacturer=KEMET, Manufacturer PN=C0402C392K4RAC7867, Package Size="0402 (1005 Metric)", Rated Voltage=16V, Temperature Coefficient=X7R, Tolerance=10%
C43 C52 C58: library part CAP_Dup1, "CAP CER 1UF 25V X7R 0603", Dielectric Type=Capacitors, Manufacturer="Wurth Electronics Inc.", Manufacturer PN=885012206076, Package Size="0603 (1608 Metric)", Rated Voltage=25V, Temperature Coefficient=X7R, Tolerance=10%
C44: library part CAP_Dup1, "CAP CER 10UF 50V X7R 1206", Dielectric Type=Capacitors, Manufacturer="Samsung Electro-Mechanics America, Inc.", Manufacturer PN=CL31B106KBHNNNE, Package Size="1206 (3216 Metric)", Rated Voltage=50V, Temperature Coefficient=X7R, Tolerance=10%
C45: library part CAP_Dup1, "CAP CER 22UF 25V X5R 1206", Dielectric Type=Capacitors, Manufacturer="Samsung Electro-Mechanics", Manufacturer PN=CL31A226KAHNNNE, Package Size="1206 (3216 Metric)", Rated Voltage=25V, Temperature Coefficient=X5R, Tolerance=20%
C46: library part CAP_Dup1, "CAP CER 27PF 25V C0G/NP0 0402", Dielectric Type=Capacitors, Manufacturer=YAGEO, Manufacturer PN=CC0402JRNPO9BN270, Package Size="0402 (1005 Metric)", Rated Voltage=25V, Temperature Coefficient="C0G, NP0", Tolerance=5%
C47 C48 C53 C54 C60 C61: library part CAP_Dup1, "CAP CER 100PF 25V X7R 0402", Dielectric Type=Capacitors, Manufacturer="Wurth Electronics Inc.", Manufacturer PN=885012205038, Package Size="0402 (1005 Metric)", Rated Voltage=25V, Temperature Coefficient=X7R, Tolerance=10%
C49 C55 C62: library part CAP_Dup1, "CAP CER 0.47UF 25V X7R 0603", Dielectric Type=Capacitors, Manufacturer="Wurth Electronics Inc.", Manufacturer PN=885012206075, Package Size="0603 (1608 Metric)", Rated Voltage=25V, Temperature Coefficient=X7R, Tolerance=10%
C50: library part CAP_Dup1, "CAP CER 4700PF 16V X7R 0402", Dielectric Type=Capacitors, Manufacturer="Wurth Electronics Inc.", Manufacturer PN=885012205029, Package Size="0402 (1005 Metric)", Rated Voltage=16V, Temperature Coefficient=X7R, Tolerance=10%
C51 C59 C65: library part CAP_Dup1, "CAP CER 10000PF 100V X7R 0603", Dielectric Type=Capacitors, Manufacturer=YAGEO, Manufacturer PN=CC0603KRX7R0BB103, Package Size="0603 (1608 Metric)", Rated Voltage=100V, Temperature Coefficient=X7R, Tolerance=20%
C57 C64: library part CAP_Dup1, "CAP CER 2.2UF 10V X5R 0402", Dielectric Type=Capacitors, Manufacturer="Wurth Electronics Inc.", Manufacturer PN=885012105013, Package Size="0402 (1005 Metric)", Rated Voltage=10V, Temperature Coefficient=X5R, Tolerance=20%
C66: library part CAP_Dup1, "CAP CER 10000PF 10V X7R 0402", Dielectric Type=Capacitors, Manufacturer="Wurth Electronics Inc.", Manufacturer PN=885012205012, Package Size="0402 (1005 Metric)", Rated Voltage=10V, Temperature Coefficient=X7R, Tolerance=10%
C67 C68 C69: library part CAP, "CAP CER 10PF 10V C0G/NP0 0402", Dielectric Type=Capacitors, Manufacturer="Wurth Electronics Inc.", Manufacturer PN=885012005007, Package Size="0402 (1005 Metric)", Rated Voltage=10V, Temperature Coefficient="C0G, NP0", Tolerance=5%
C70: library part CAP_4, "CAP CER 0.1UF 16V X7R 0402", Dielectric Type=Capacitors, Manufacturer="Wurth Electronics Inc.", Manufacturer PN=885012205037, Package Size="0402 (1005 Metric)", Rated Voltage=16V, Temperature Coefficient=X7R, Tolerance=10%
D1: library part DIODE_SCHOTTKY_0, "DIODE SCHOTTKY 20V 1A STMITEFLAT", Manufacturer=STMicroelectronics, Package Size=DO-222AA, Rated Voltage="430mV @ 1A"
D2: library part LED_BICOLOR, "LED GREEN/RED CLEAR 4PLCC SMD", Manufacturer="Wurth Electronics Inc.", Manufacturer PN=150141RV73100, Package Size=4-PLCC
D3 D5: library part LED, "LED GREEN 0402 SMD", Manufacturer="Everlight Electronics", Manufacturer PN=16-213SYGC/S530-E3/TR8, Package Size="0402 (1005 Metric)"
D4: library part LED, "DIO, Rectangle with Flat Top, 1.00mm x 0.50mm, VLMS1500-GS08, 20mA, --, --, 0402 (1005 Metric)", Manufacturer="Vishay Semiconductor Opto Division", Manufacturer PN=VLMS1500-GS08, Package Size="0402 (1005 Metric)"
D6 D8 D9: library part DIODE_SCHOTTKY_0, "DIODE SCHOTTKY 60V 500MA SOD123", Manufacturer=STMicroelectronics, Package Size=SOD-123, Rated Voltage="530mV @ 500mA"
D7: library part DIODE_SCHOTTKY_0, "DIODE SCHOTTKY 40V 1A STMITE", Manufacturer=STMicroelectronics, Package Size=DO-216AA, Rated Voltage="460mV @ 1A"
D10 D11 D12 D13 D14 D15 D16 D17 D18 D19: library part DIODE_SCHOTTKY_0, "DIODE SCHOTTKY 30V 300MA SOD523", Manufacturer=STMicroelectronics, Package Size="SC-79, SOD-523", Rated Voltage="530mV @ 300mA"
D20: library part DIODE_TRANSIL_UNI_0, "TVS DIODE 26VWM 53.5VC DO222AA", Manufacturer=STMicroelectronics, Manufacturer PN=SMM4F26A-TR, Package Size="DO-216AA FLAT"
F1: library part FUSE, "FUSE BOARD MNT 250MA 32VDC 0402", Manufacturer="Littelfuse Inc.", Manufacturer Code=0435.250KRS, Package Size="0.039\" L x 0.020\" W x 0.013\" H (0.99mm x 0.51mm x 0.33mm)"
J1 J2 J4: library part CON4, "SOLDER PADS"
J3 J8: library part CON5, "SOLDER PADS"
J5 J6: "SOLDER PADS"
J7: library part CON3, "SOLDER PADS"
JP1 JP2 JP3: library part SHORT, "2 PIN SHORTED TO CONNECT DIFFERENT NETS"
L1: library part IND_FB, "FERRITE BEAD 600 OHM 0402 1LN", Manufacturer="Murata Electronics North America", Manufacturer PN=BLM15BX601SN1D, Package Size="0402 (1005 Metric)"
L2: library part IND, "Fixed Inductors LPS4018 Low Profile 33uH 0.8A 20% SMD", Manufacturer=Coilcraft, Manufacturer PN=LPS4018-333MRB, Package Size=3.9x3.9x1.7, Tolerance=20%
Q1: library part BJT_NPN_BEC, "TRANS NPN 60V 1A SOT-23", Manufacturer=STMicroelectronics, Package Size="TO-236-3, SC-59, SOT-23-3"
Q2 Q3 Q4 Q5 Q6 Q7: library part MOSFET_N_DIODE_SSSGDDDD, "N-channel 60 V, 1.9 mO typ., 120 A STripFET™ F7", Manufacturer=STMicroelectronics, Package Size="PowerFLAT 5x6", Rated Voltage=60V
R1: library part RES, "RES SMD 120 OHM 1% 1/16W 0402", Manufacturer=Yageo, Manufacturer PN=RC0402FR-07120RL, Package Size="0402 (1005 Metric)", Rated Power="0.063W, 1/16W", Temperature Coefficient=100ppm/C, Tolerance=1%
R2: library part POT, "TRIMMER 10K OHM 0.5W PC PIN", Manufacturer="Bourns Inc.", Manufacturer PN=3386P-1-103TLF, Package Size="Square - 0.375\" x 0.375\" Face x 0.190\" H (9.53mm x 9.53mm x 4.83mm)", Rated Power="0.5W, 1/2W", Temperature Coefficient=100ppm/C, Tolerance=10%
R3 R10 R12 R16 R35 R39 R41 R45 R46 R48 R52 R53 R71 R72 R73: library part RES, "RES SMD 10K OHM 1% 1/16W 0402", Manufacturer=Yageo, Manufacturer PN=RC0402FR-0710KL, Package Size="0402 (1005 Metric)", Rated Power="0.063W, 1/16W", Temperature Coefficient=100ppm/C, Tolerance=1%
R4 R8 R9 R18 R20: library part RES, "RES SMD 100 OHM 1% 1/16W 0402", Manufacturer="TE Connectivity Passive Product", Manufacturer PN=CRG0402F100R, Package Size="0402 (1005 Metric)", Rated Power="0.063W, 1/16W", Temperature Coefficient=100ppm/C, Tolerance=1%
R5 R67 R69 R70: library part RES, "RES SMD 1.5K OHM 1% 1/16W 0402", Manufacturer=Yageo, Manufacturer PN=RC0402FR-071K5L, Package Size="0402 (1005 Metric)", Rated Power="0.063W, 1/16W", Temperature Coefficient=100ppm/C, Tolerance=1%
R6: library part RES, "RES SMD 36K OHM 1% 1/16W 0402", Manufacturer=Yageo, Manufacturer PN=RC0402FR-0736KL, Package Size="0402 (1005 Metric)", Rated Power="0.063W, 1/16W", Temperature Coefficient=100ppm/C, Tolerance=1%
R7 R13 R15: library part RES, "RES SMD 100K OHM 1% 1/16W 0402", Manufacturer="TE Connectivity Passive Product", Manufacturer PN=CRG0402F100K, Package Size="0402 (1005 Metric)", Rated Power="0.063W, 1/16W", Temperature Coefficient=100ppm/C, Tolerance=1%
R11 R26: library part RES, "RES SMD 0 OHM JUMPER 1/16W 0402", Manufacturer="Vishay Dale", Manufacturer PN=CRCW04020000Z0ED, Package Size="0402 (1005 Metric)", Rated Power="0.063W, 1/16W", Temperature Coefficient=-, Tolerance=Jumper
R14: library part RES, "RES SMD 2.7K OHM 1% 1/16W 0402", Manufacturer=Yageo, Manufacturer PN=RC0402FR-072K7L, Package Size="0402 (1005 Metric)", Rated Power="0.063W, 1/16W", Temperature Coefficient=100ppm/C, Tolerance=1%
R17: library part RES, "RES SMD 0402 - NOT MOUNTED", Package Size="0402 (1005 Metric)"
R19 R22 R30 R60: library part RES, "RES SMD 4.7K OHM 1% 1/16W 0402", Manufacturer="TE Connectivity Passive Product", Manufacturer PN=CRG0402F4K7, Package Size="0402 (1005 Metric)", Rated Power="0.063W, 1/16W", Temperature Coefficient=100ppm/C, Tolerance=1%
R21: library part RES, "RES SMD 1K OHM 1% 1/16W 0402", Manufacturer=Yageo, Manufacturer PN=RC0402FR-071KL, Package Size="0402 (1005 Metric)", Rated Power="0.063W, 1/16W", Temperature Coefficient=100ppm/C, Tolerance=1%
R23 R24: library part RES, "RES SMD 0 OHM JUMPER 1/10W 0603", Manufacturer="Panasonic Electronic Components", Manufacturer PN=ERJ-3GEY0R00V, Package Size="0603 (1608 Metric)", Rated Power="0.1W, 1/10W", Temperature Coefficient=-, Tolerance=Jumper
R27: library part RES, "RES SMD 220 OHM 1% 1/16W 0402", Manufacturer=Yageo, Manufacturer PN=RC0402FR-07220RL, Package Size="0402 (1005 Metric)", Rated Power="0.063W, 1/16W", Temperature Coefficient=100ppm/C, Tolerance=1%
R28 R29: library part RES, "RES SMD 510 OHM 1% 1/16W 0402", Manufacturer=Yageo, Manufacturer PN=RC0402FR-07510RL, Package Size="0402 (1005 Metric)", Rated Power="0.063W, 1/16W", Temperature Coefficient=100ppm/C, Tolerance=1%
R31: library part RES, "RES SMD 62 OHM 1% 1/16W 0402", Manufacturer=Yageo, Manufacturer PN=RC0402FR-0762RL, Package Size="0402 (1005 Metric)", Rated Power="0.063W, 1/16W", Temperature Coefficient=100ppm/C, Tolerance=1%
R32: library part RES, "RES SMD 34.8K OHM 1% 1/16W 0402", Manufacturer=Yageo, Manufacturer PN=RC0402FR-0734K8L, Package Size="0402 (1005 Metric)", Rated Power="0.063W, 1/16W", Temperature Coefficient=100ppm/C, Tolerance=1%
R33: library part RES, "RES SMD 300 OHM 1% 1/16W 0402", Manufacturer=Yageo, Manufacturer PN=RC0402FR-07300RL, Package Size="0402 (1005 Metric)", Rated Power="0.063W, 1/16W", Temperature Coefficient=100ppm/C, Tolerance=1%
R34 R38 R40 R43 R47 R50: library part RES, "RES SMD 33 OHM 1% 1/10W 0603", Manufacturer=Yageo, Manufacturer PN=9C06031A33R0FKHFT, Package Size="0603 (1608 Metric)", Rated Power="0.1W, 1/10W", Temperature Coefficient=100ppm/C, Tolerance=1%
R36: library part RES, "RES SMD 8.2K OHM 5% 1/16W 0402", Manufacturer=Yageo, Manufacturer PN=RC0402JR-078K2L, Package Size="0402 (1005 Metric)", Rated Power="0.063W, 1/16W", Temperature Coefficient=100ppm/C, Tolerance=5%
R37 R44 R51: library part RES, "RES SMD 1 OHM 5% 1/8W 0805", Manufacturer="Panasonic Electronic Components", Manufacturer PN=ERJ-6GEYJ1R0V, Package Size="0805 (2012 Metric)", Rated Power="0.125W, 1/8W", Temperature Coefficient="-100/ +600ppm/C", Tolerance=5%
R42: library part RES, "RES SMD 52.3K OHM 1% 1/16W 0402", Manufacturer="Samsung Electro-Mechanics", Manufacturer PN=RC1005F5232CS, Package Size="0402 (1005 Metric)", Rated Power="0.063W, 1/16W", Temperature Coefficient=100ppm/C, Tolerance=1%
R49: library part RES, "RES SMD 30.9K OHM 1% 1/10W 0402", Manufacturer="Panasonic Electronic Components", Manufacturer PN=ERJ-2RKF3092X, Package Size="0402 (1005 Metric)", Rated Power="0.1W, 1/10W", Temperature Coefficient=100ppm/C, Tolerance=1%
R54 R55 R56: library part RES, "RES 0.003 OHM 1% 3W 2512", Manufacturer=ROHM, Manufacturer PN=PSR100KTQFL3L00, Package Size="2512 (6432 Metric)", Rated Power=3W, Temperature Coefficient=50ppm/C, Tolerance=1%
R57 R58 R59 R80 R81 R82: library part RES, "RES SMD 2.2K OHM 1% 1/16W 0402", Manufacturer=Yageo, Manufacturer PN=RC0402FR-072K2L, Package Size="0402 (1005 Metric)", Rated Power="0.063W, 1/16W", Temperature Coefficient=100ppm/C, Tolerance=1%
R61 R62 R63: library part RES, "RES SMD 10K OHM 1% 1/10W 0603", Manufacturer=Yageo, Manufacturer PN=RC0603FR-0710KL, Package Size="0603 (1608 Metric)", Rated Power="0.1W, 1/10W", Temperature Coefficient=100ppm/C, Tolerance=1%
